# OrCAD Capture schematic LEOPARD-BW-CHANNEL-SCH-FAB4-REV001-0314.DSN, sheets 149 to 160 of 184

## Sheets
149 014_POWER OFF SEQUENCE: title: POWER OFF SEQUENCE
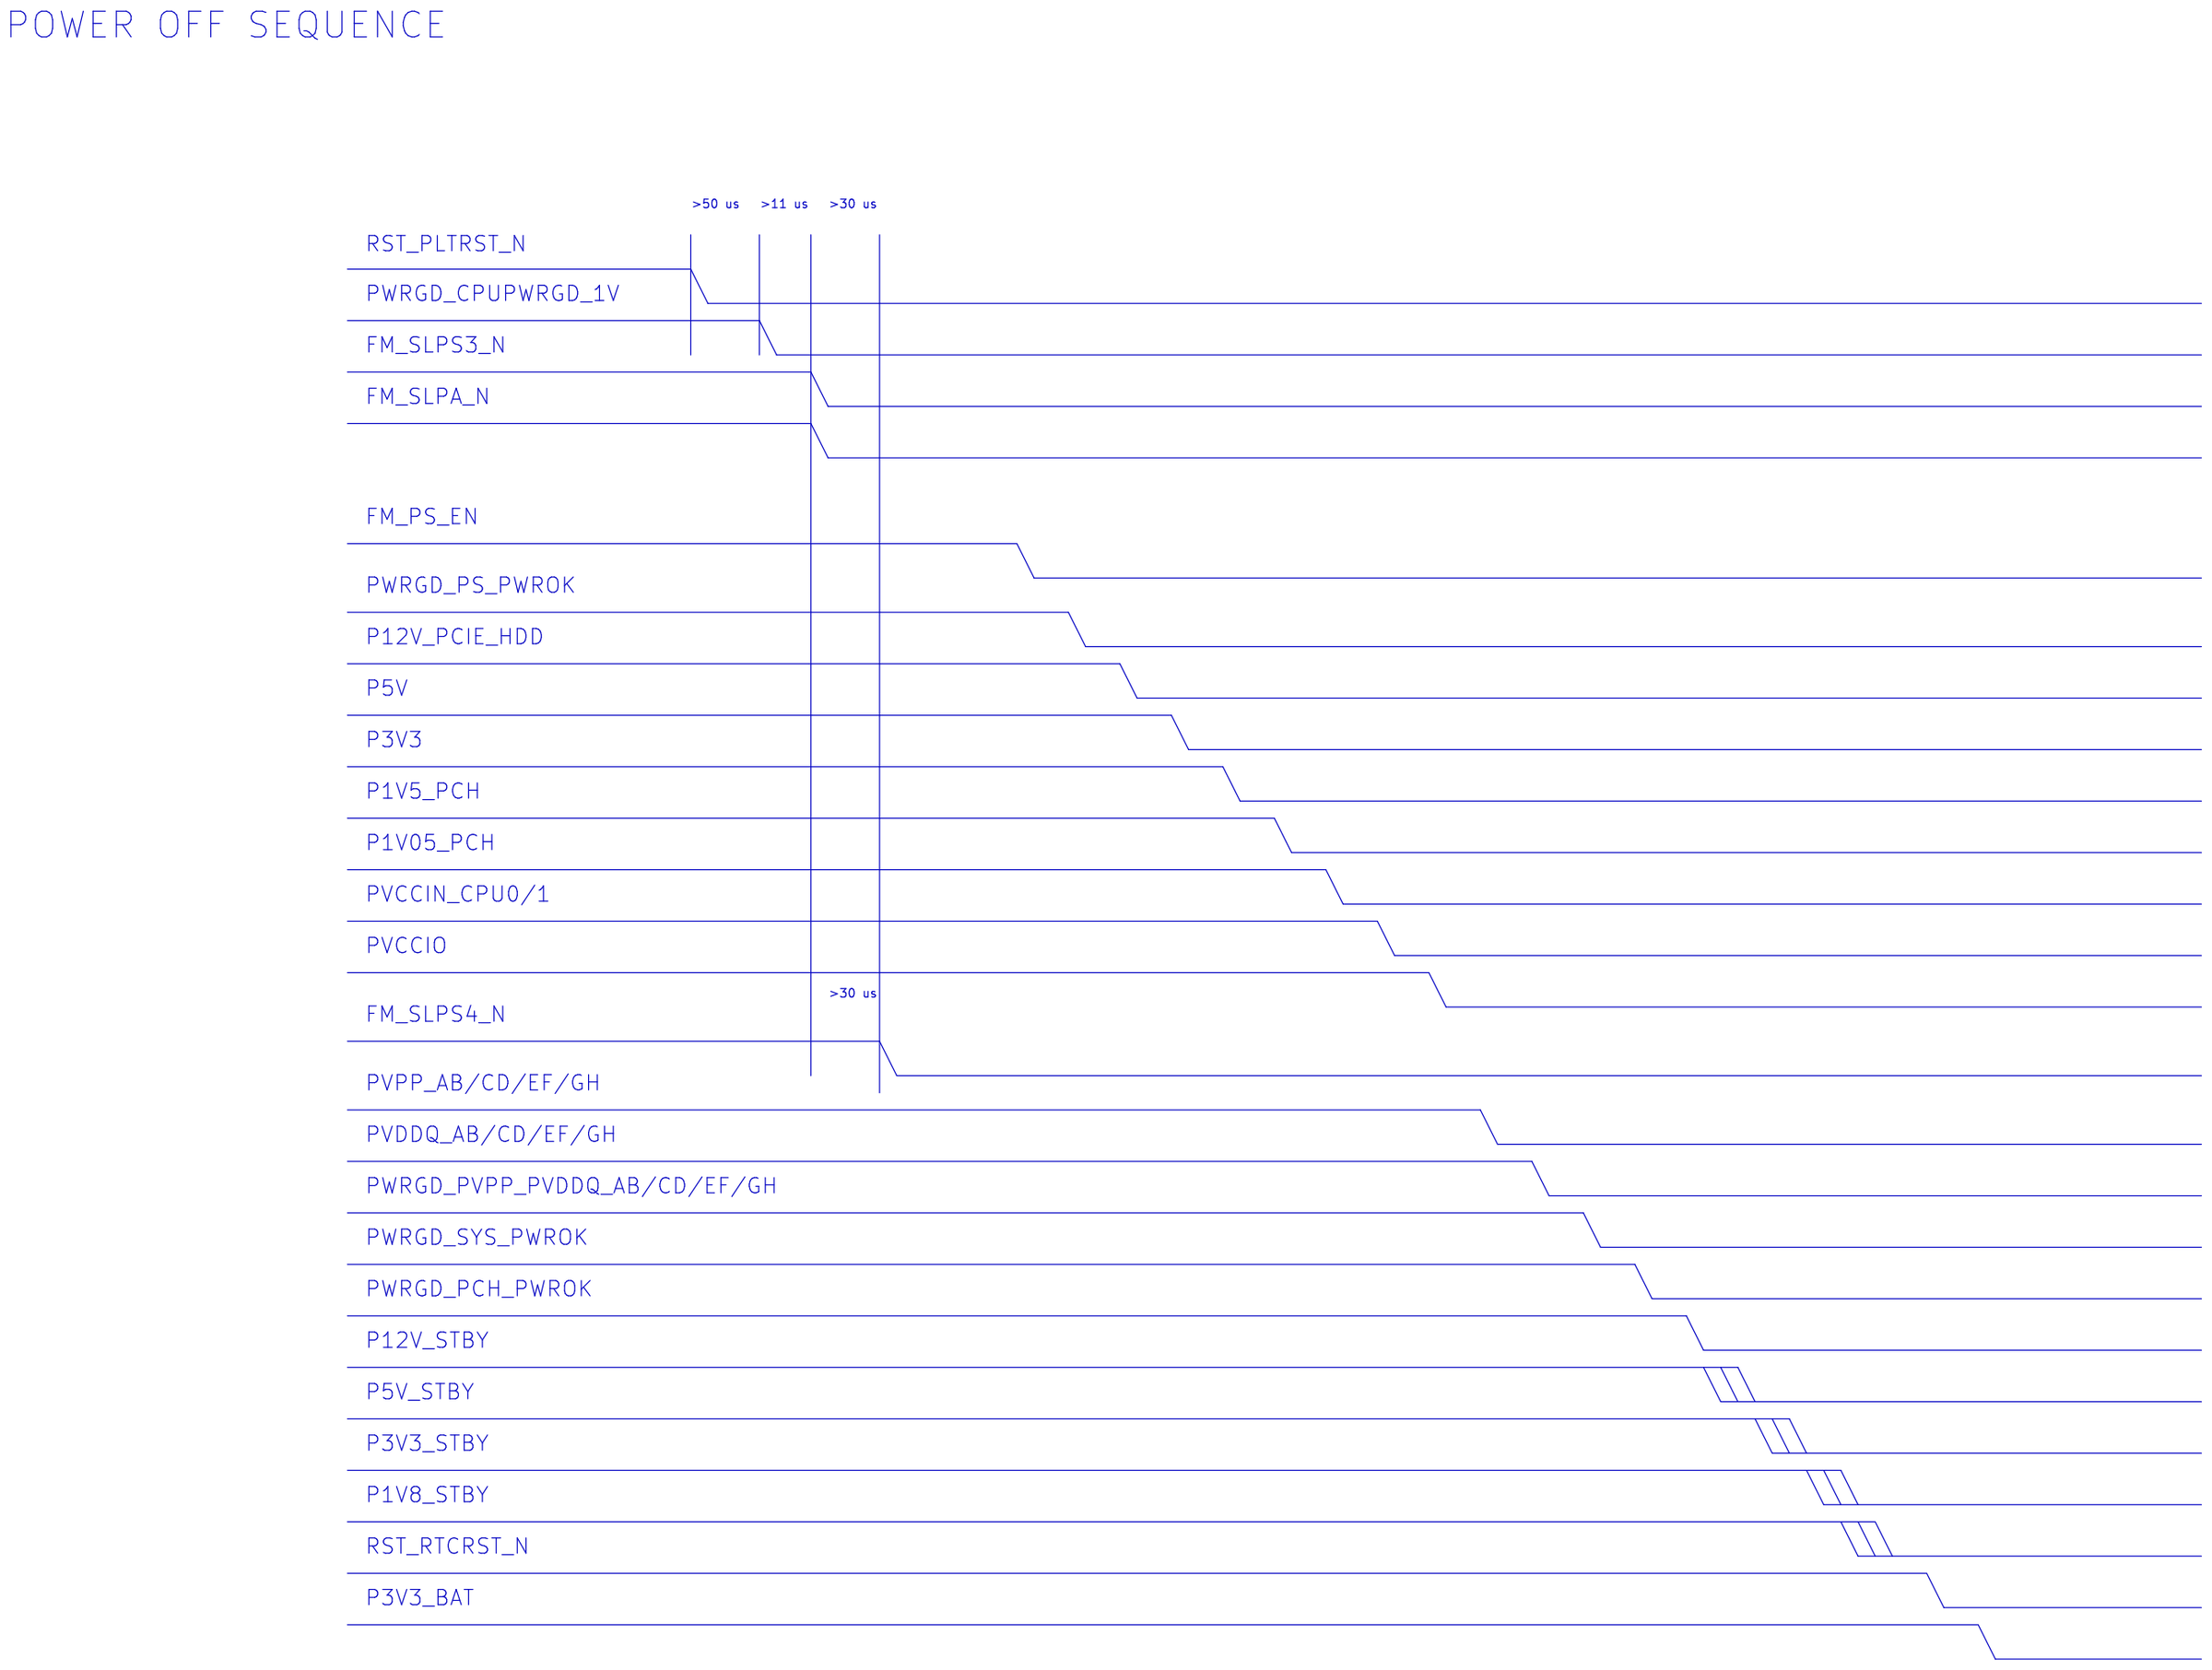
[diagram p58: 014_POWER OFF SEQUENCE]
150 013_POWER ON SEQUENCE: title: POWER ON SEQUENCE
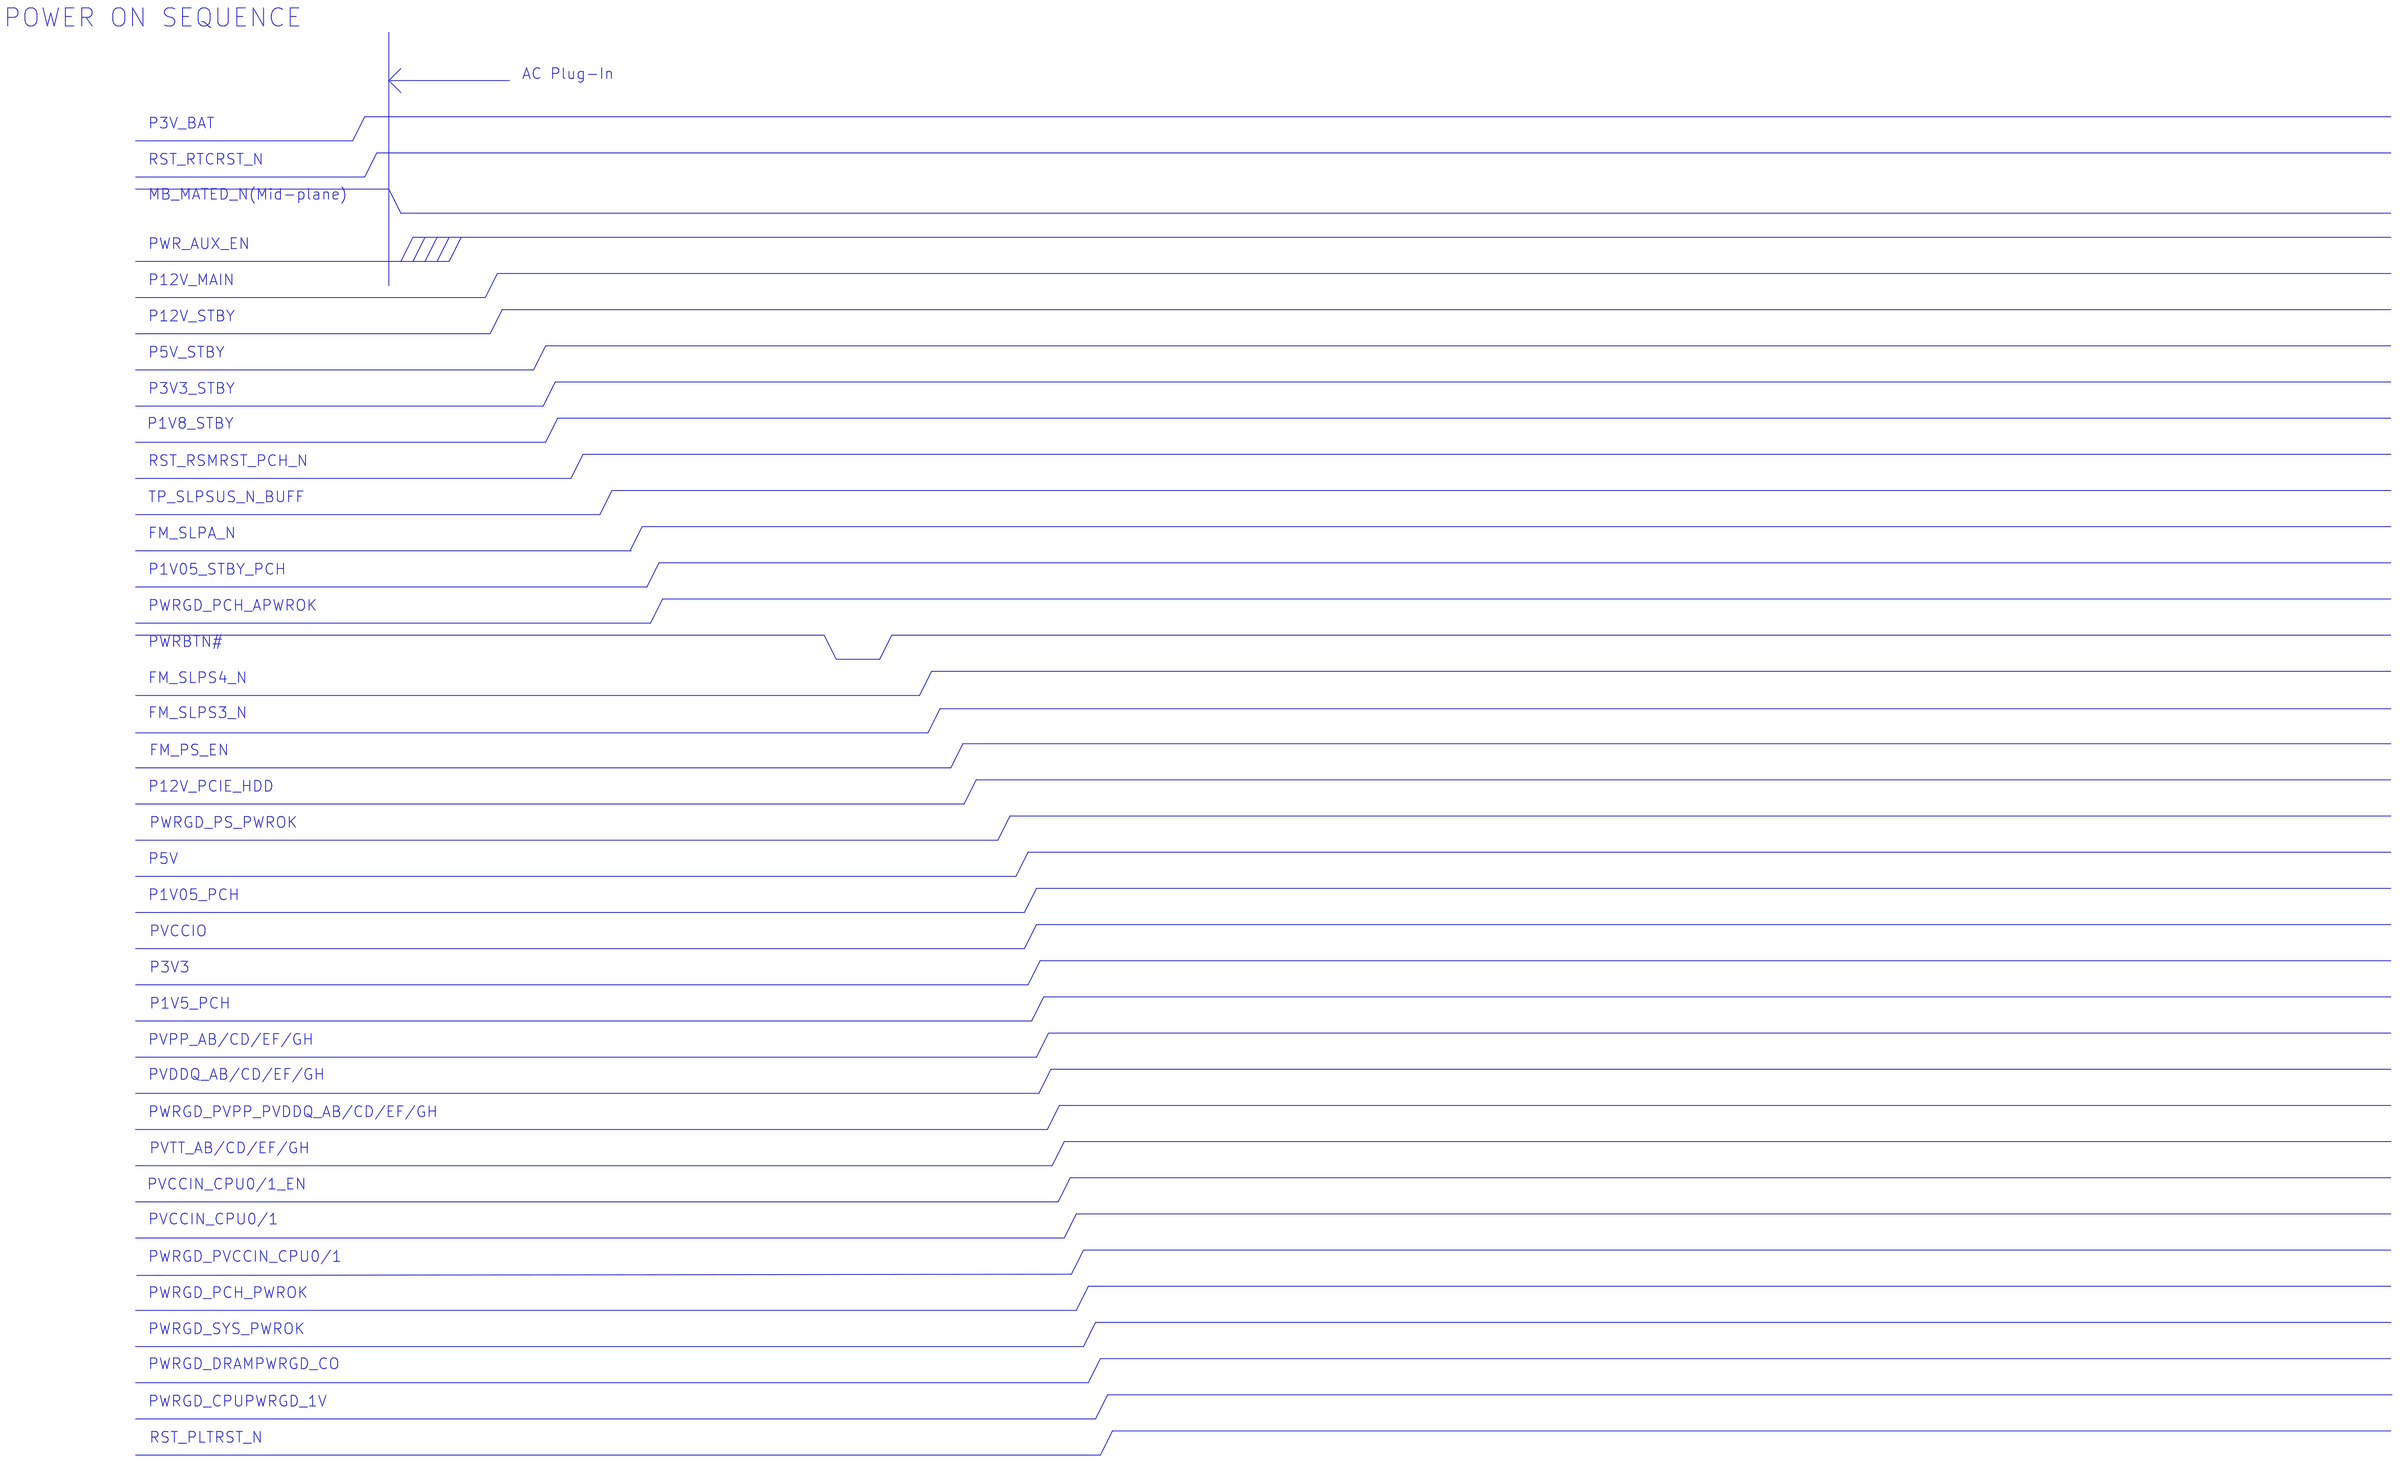
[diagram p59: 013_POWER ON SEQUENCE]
151 012_CPU XDP: title: CPU XDP
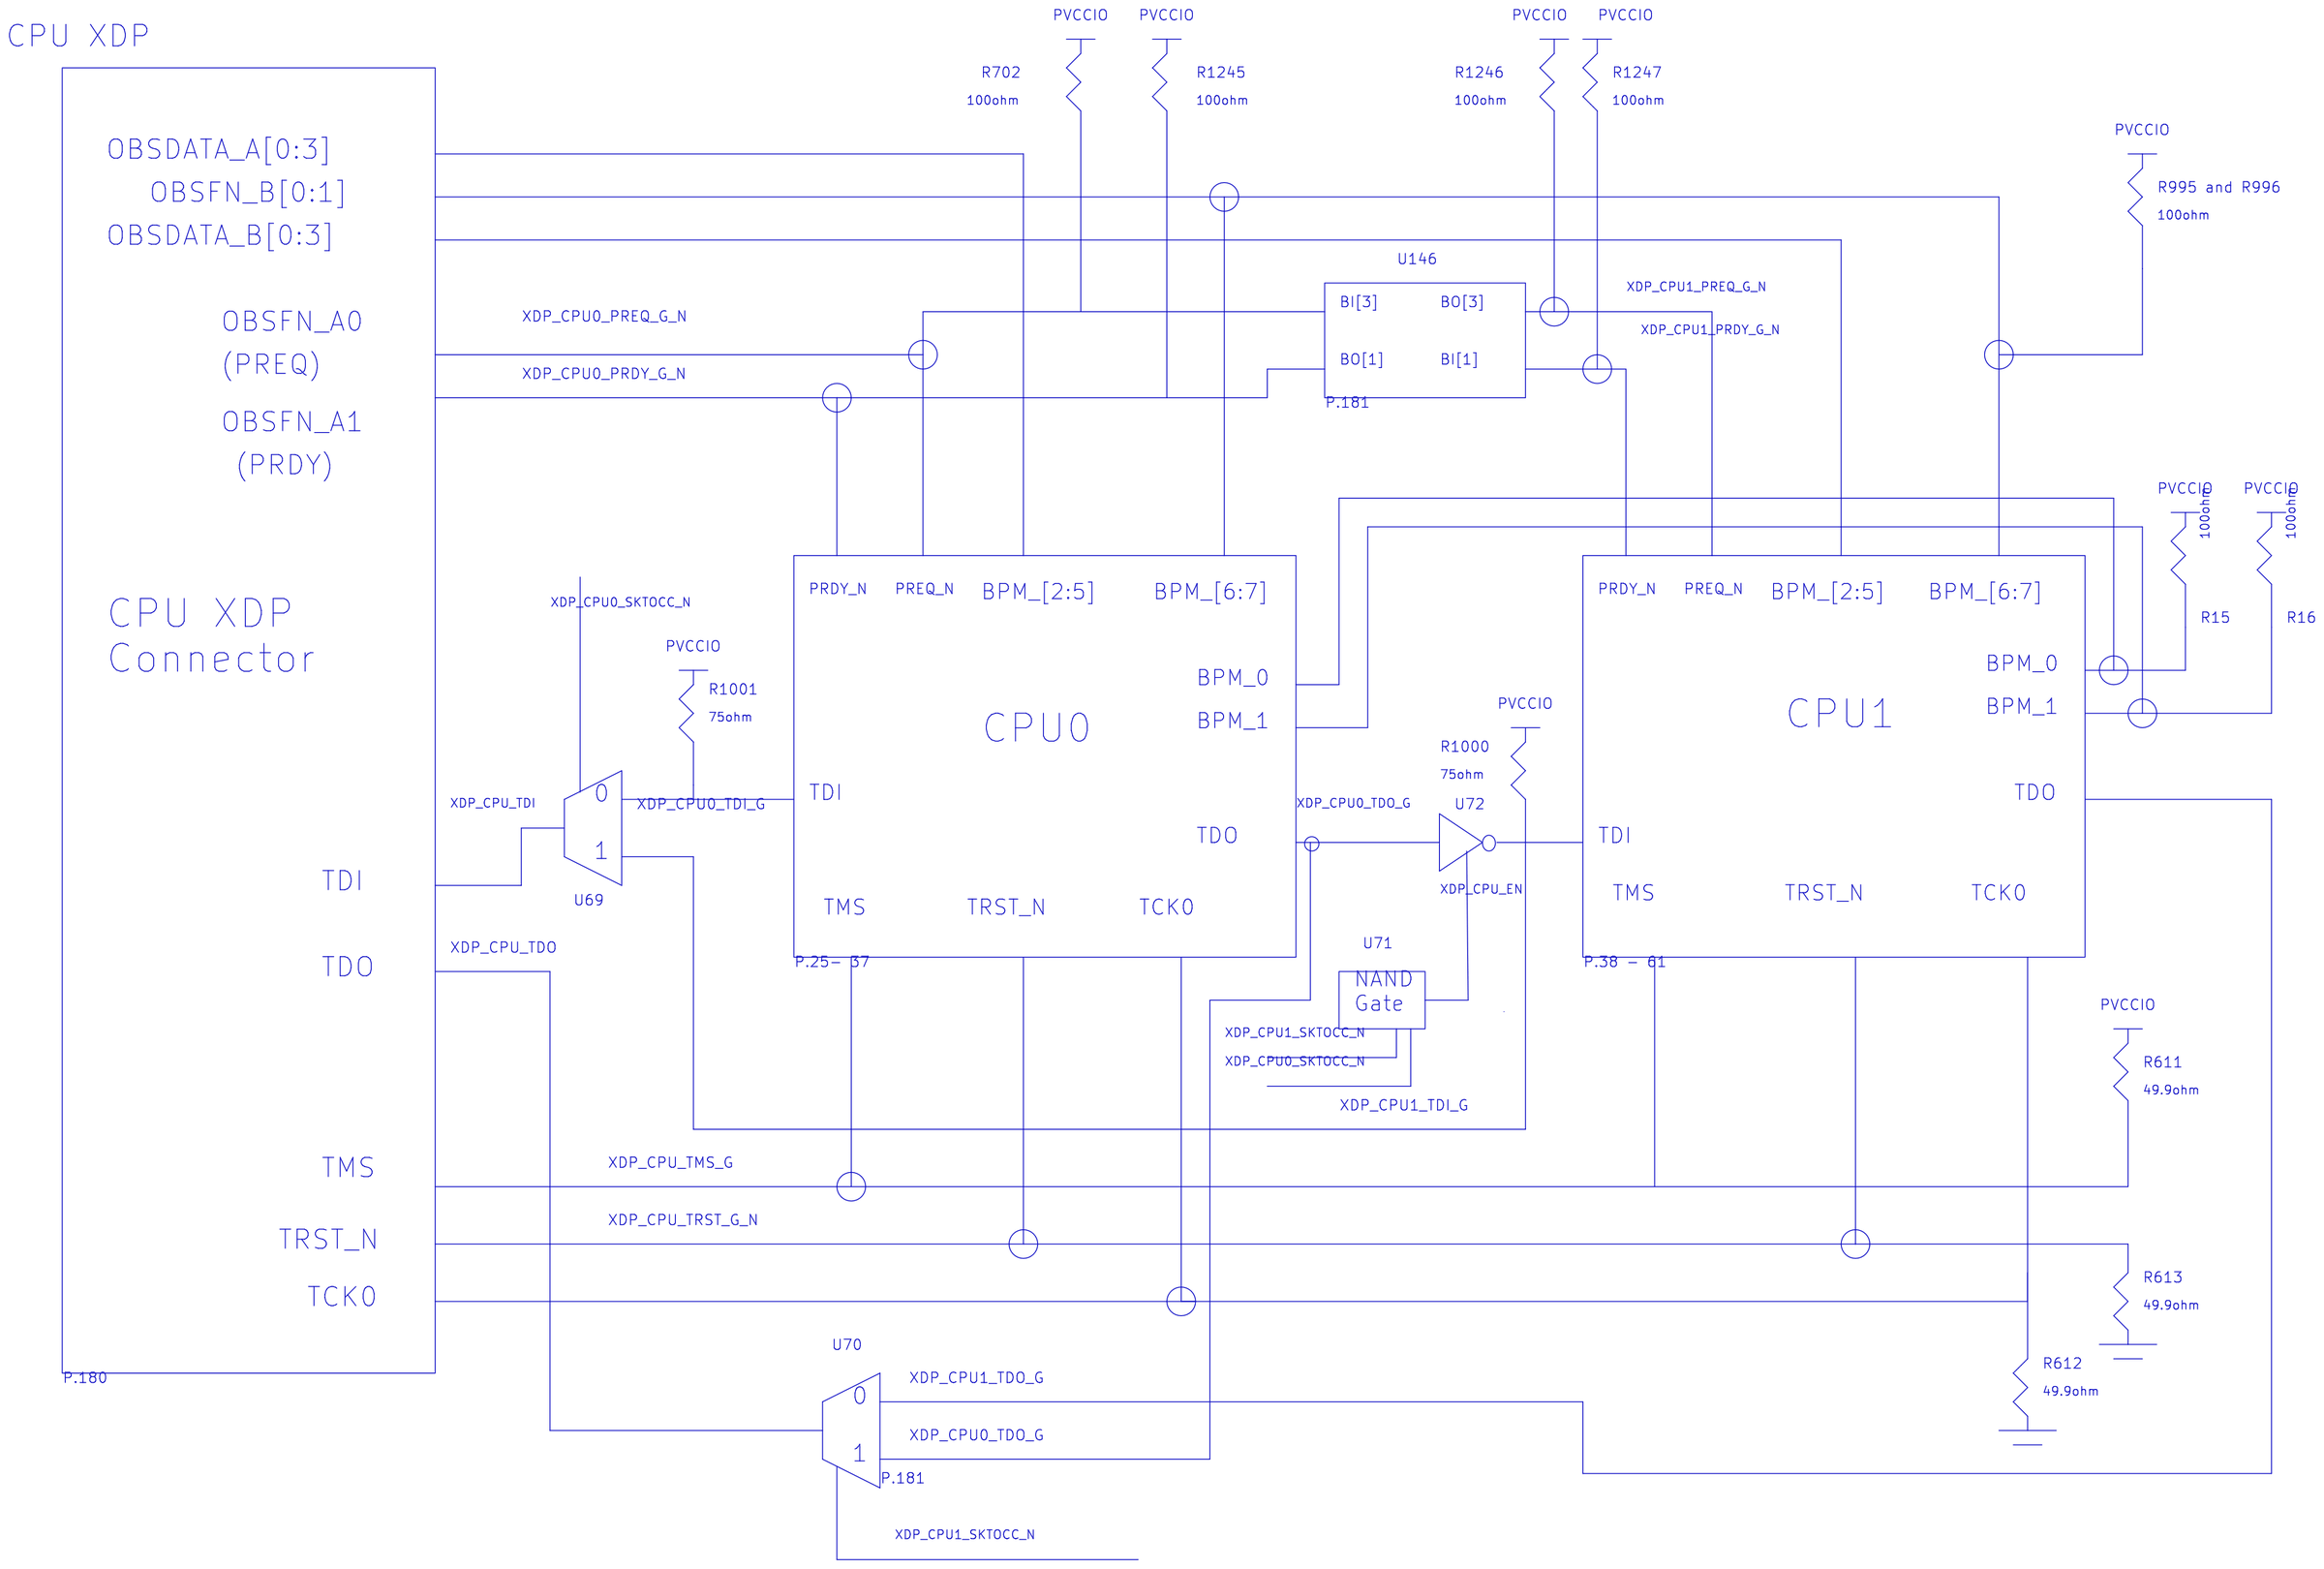
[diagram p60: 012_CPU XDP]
152 011_MEMORY WARNING AND PROTECT: title: MEMORY WARNING AND PROTECT
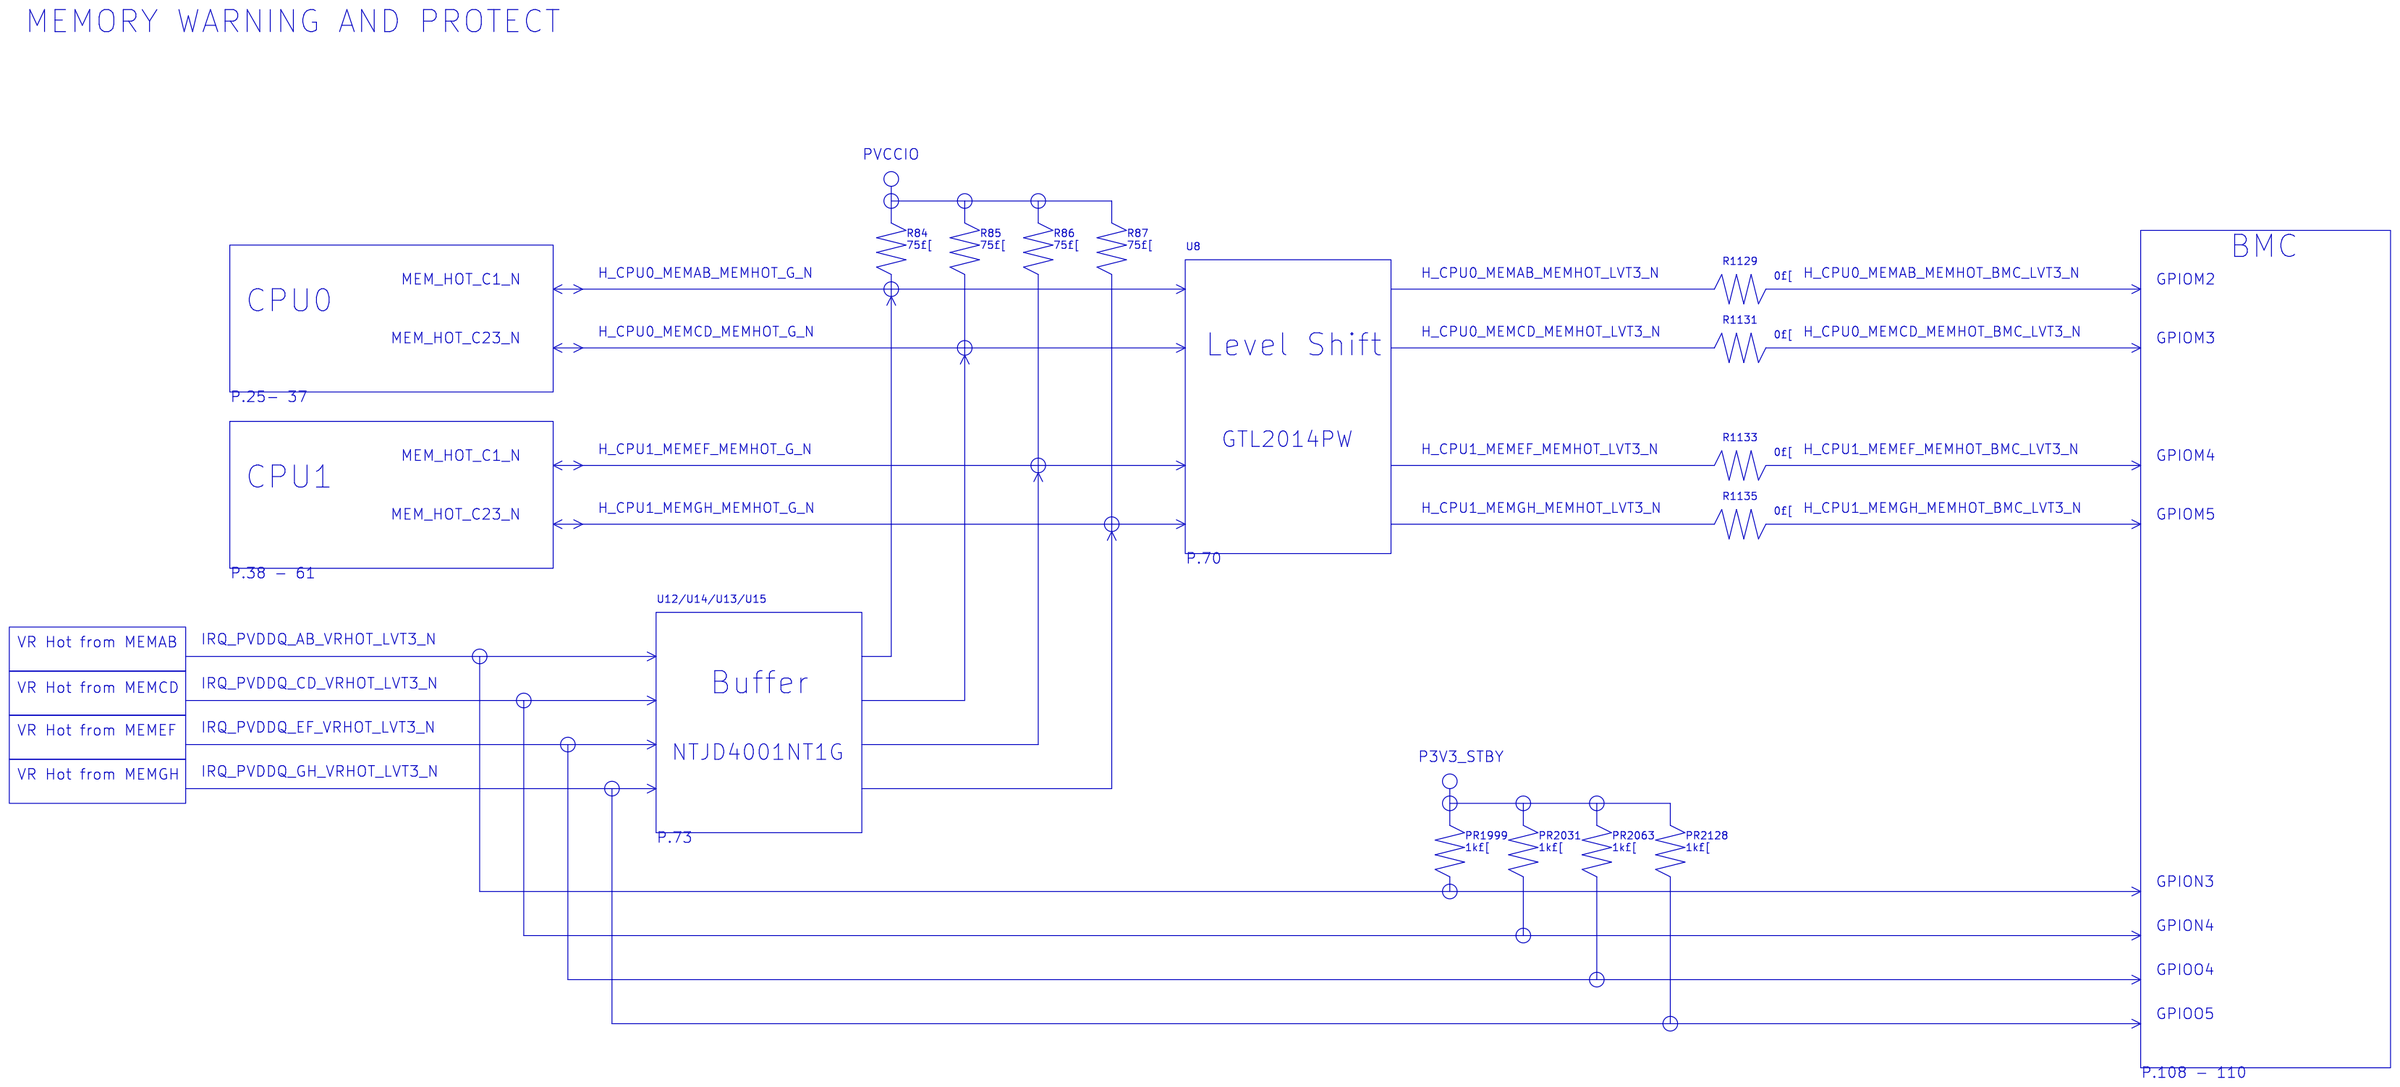
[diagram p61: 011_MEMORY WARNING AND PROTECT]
153 010_SYSTEM ERROR REPORTING: title: SYSTEM ERROR REPORTING
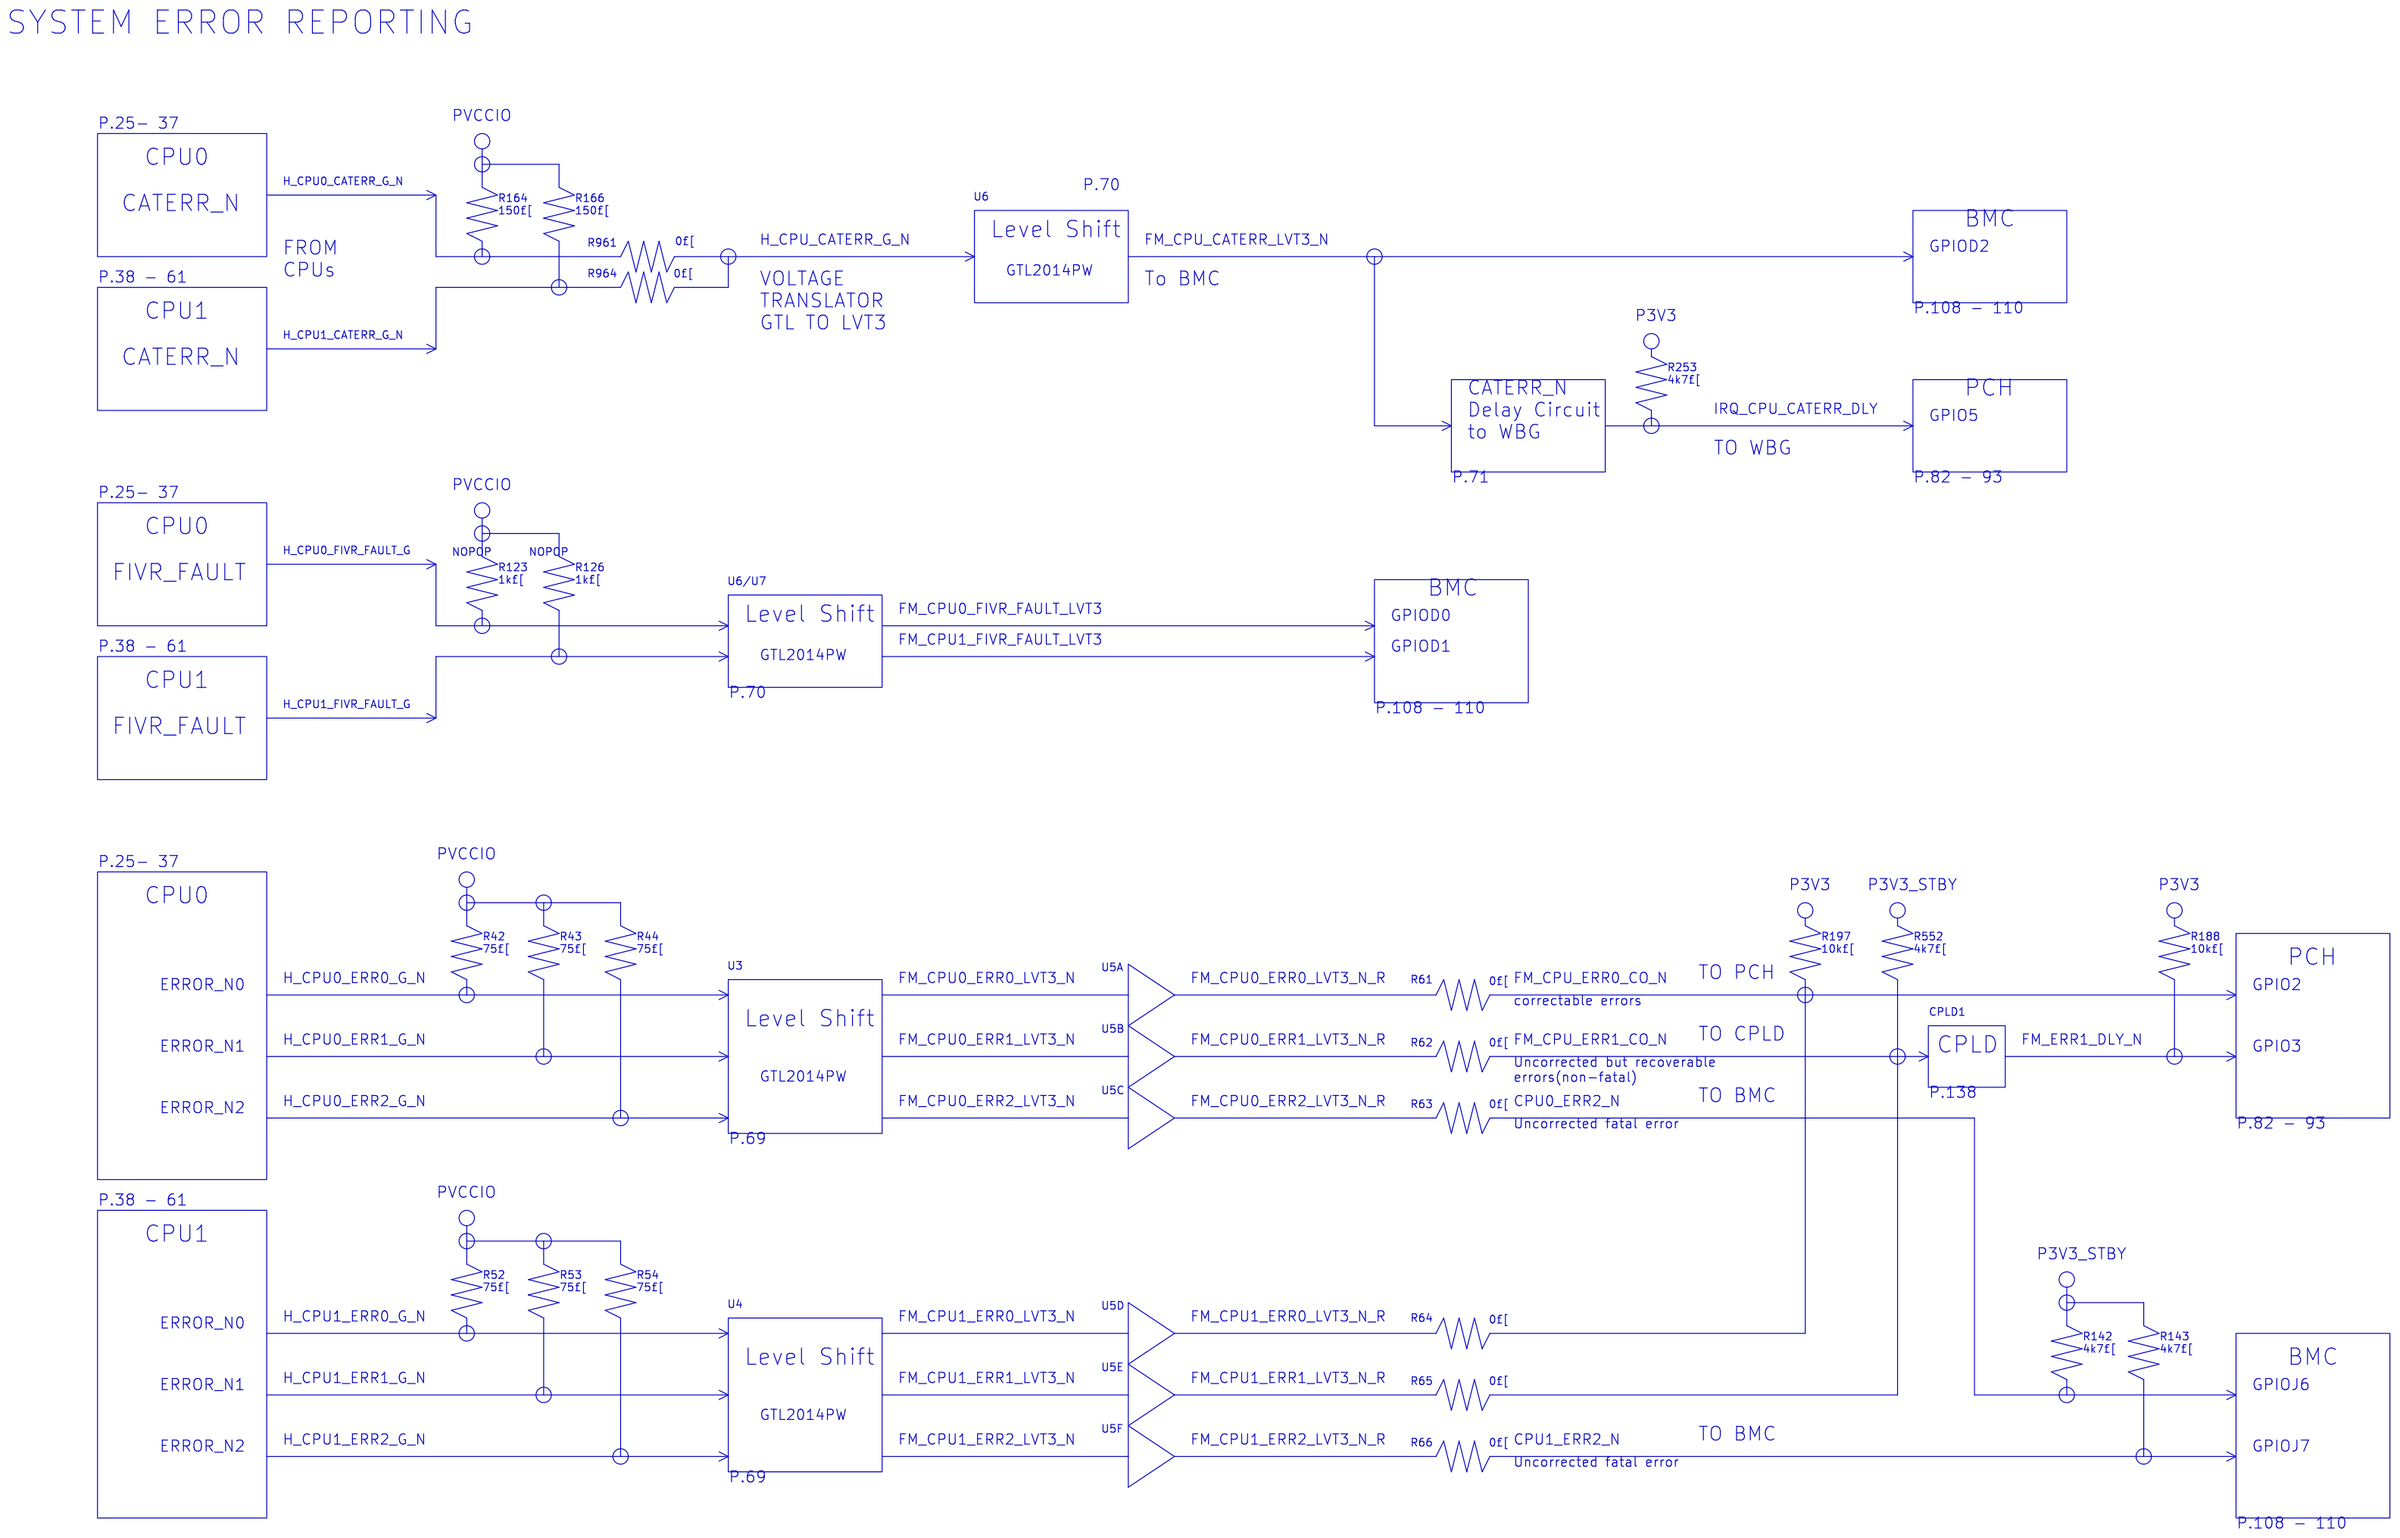
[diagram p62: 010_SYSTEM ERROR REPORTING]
154 009_SYSTEM WARNING AND PROTECT: title: SYSTEM WARNING AND PROTECT
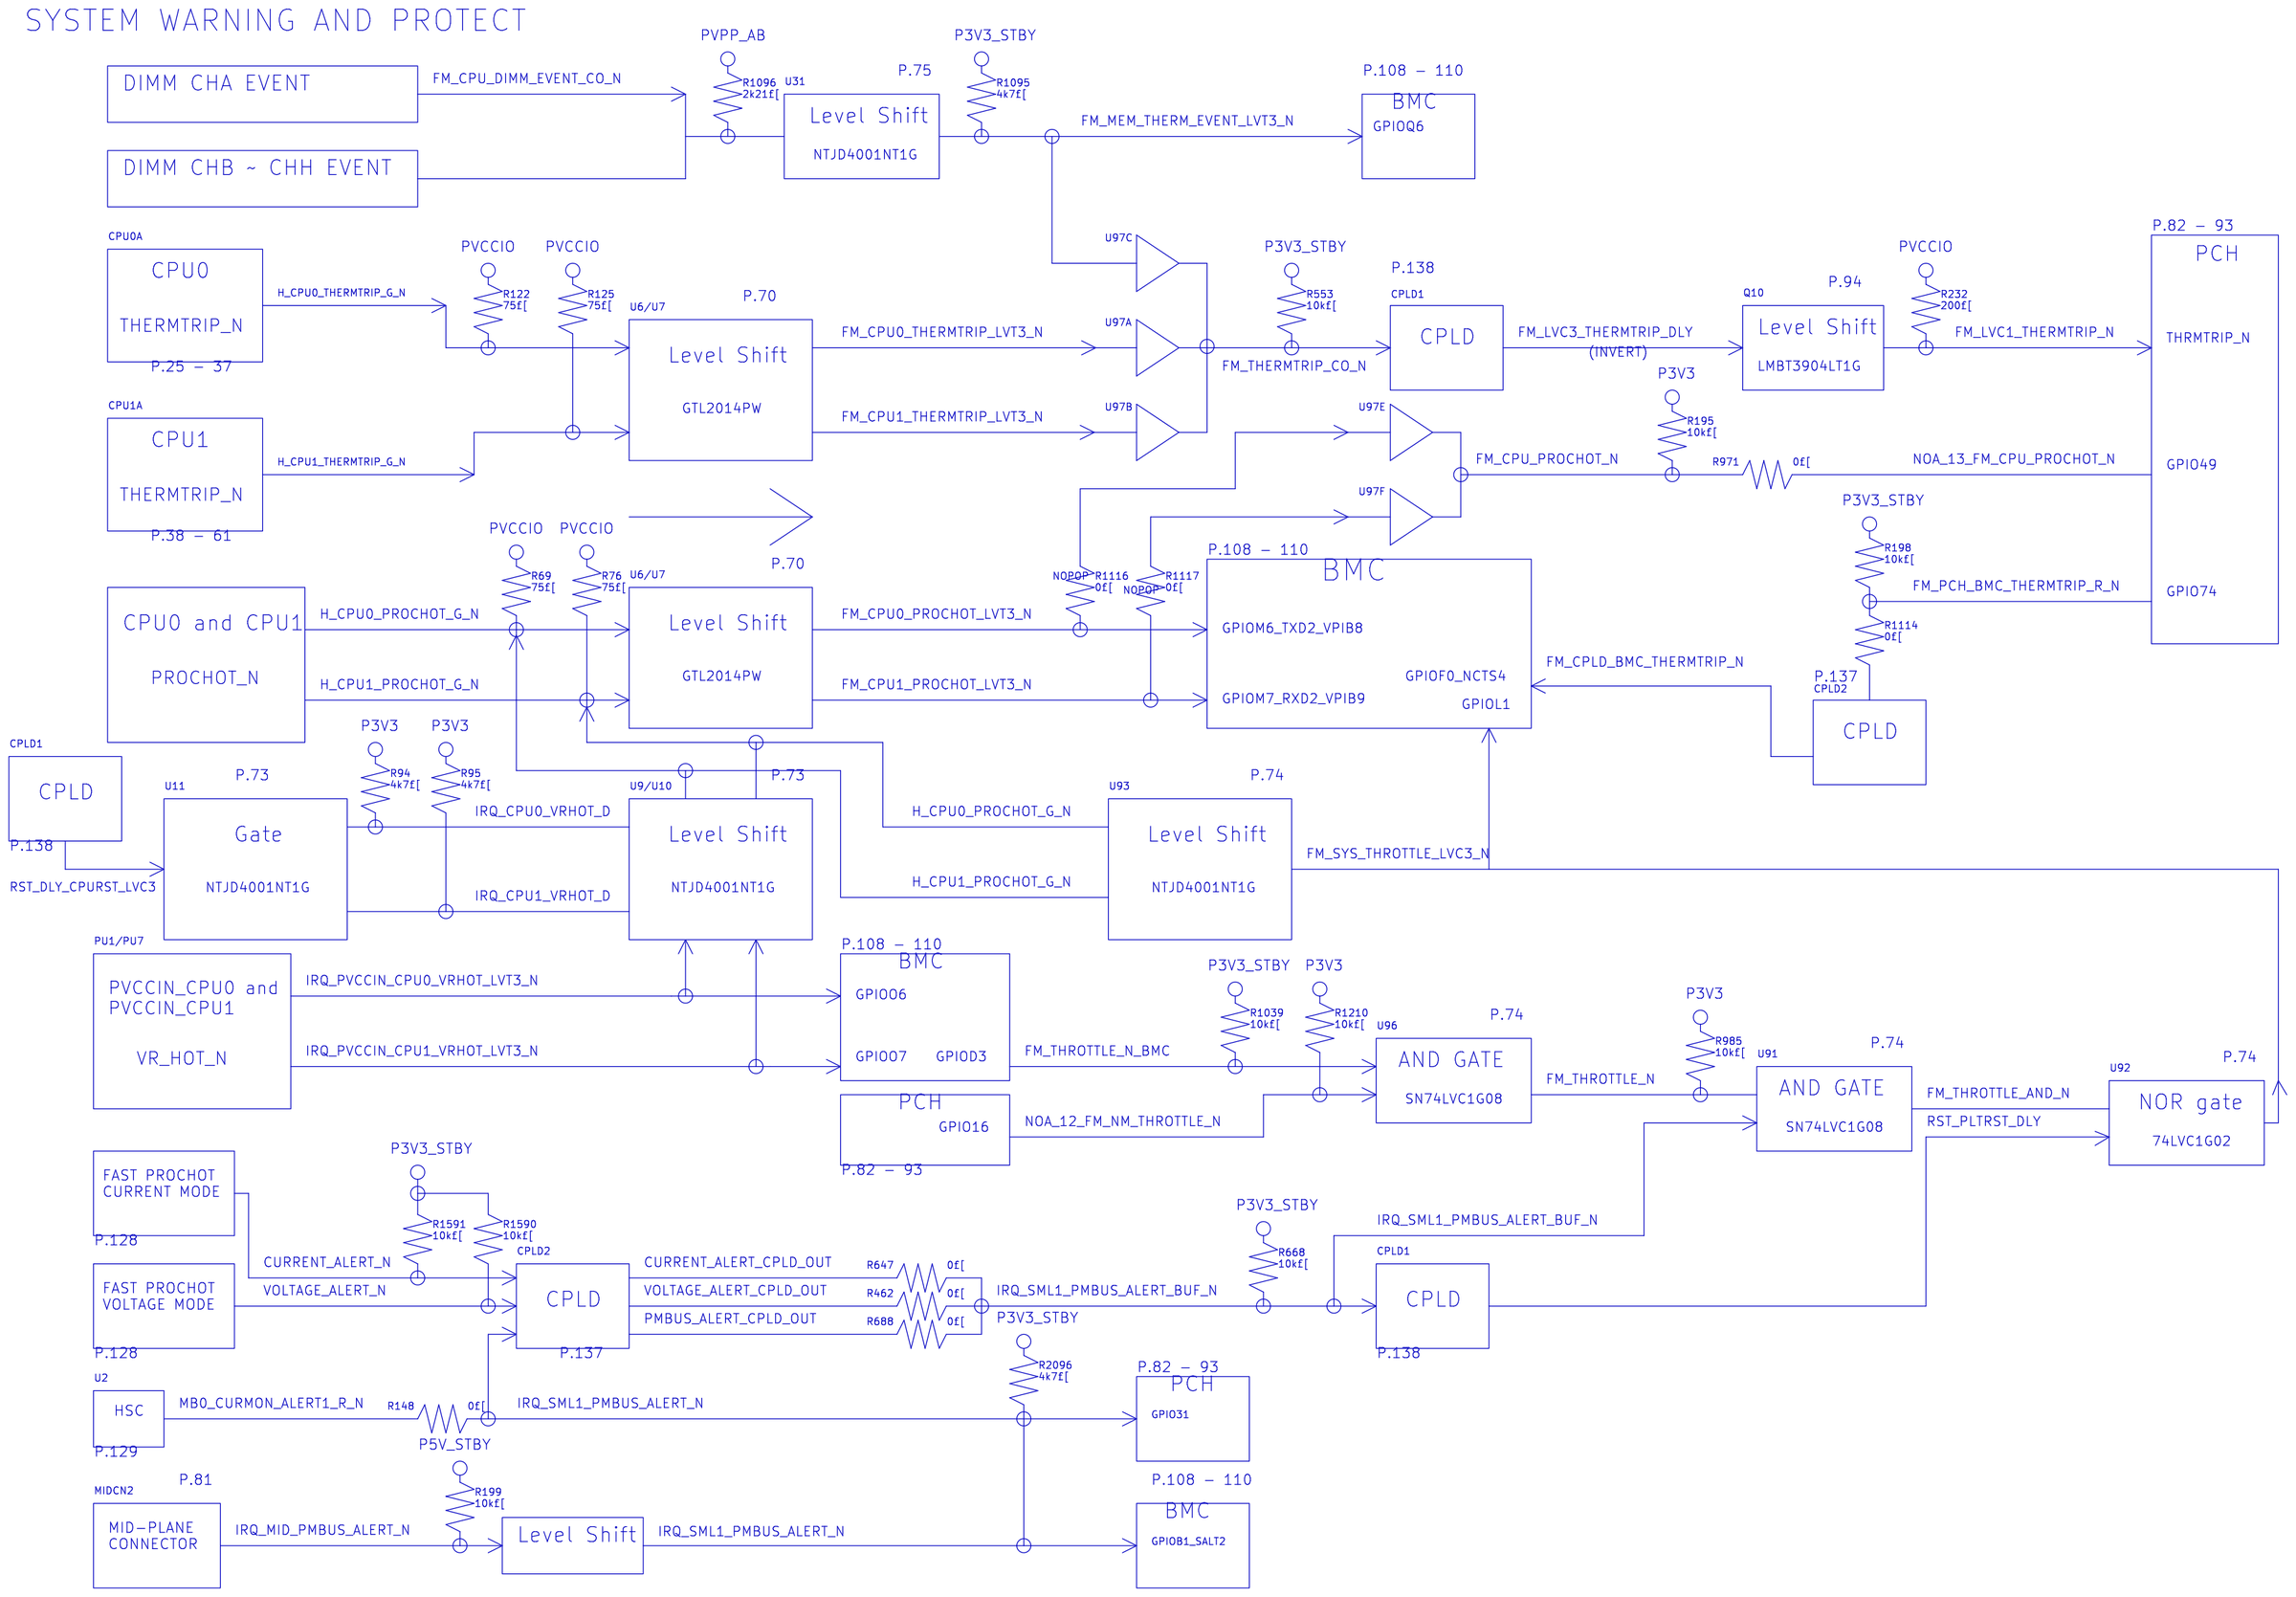
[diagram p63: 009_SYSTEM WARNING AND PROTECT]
155 005_POWER DISTRIBUTION DIAGRAM: title: POWER DISTRIBUTION DIAGRAM
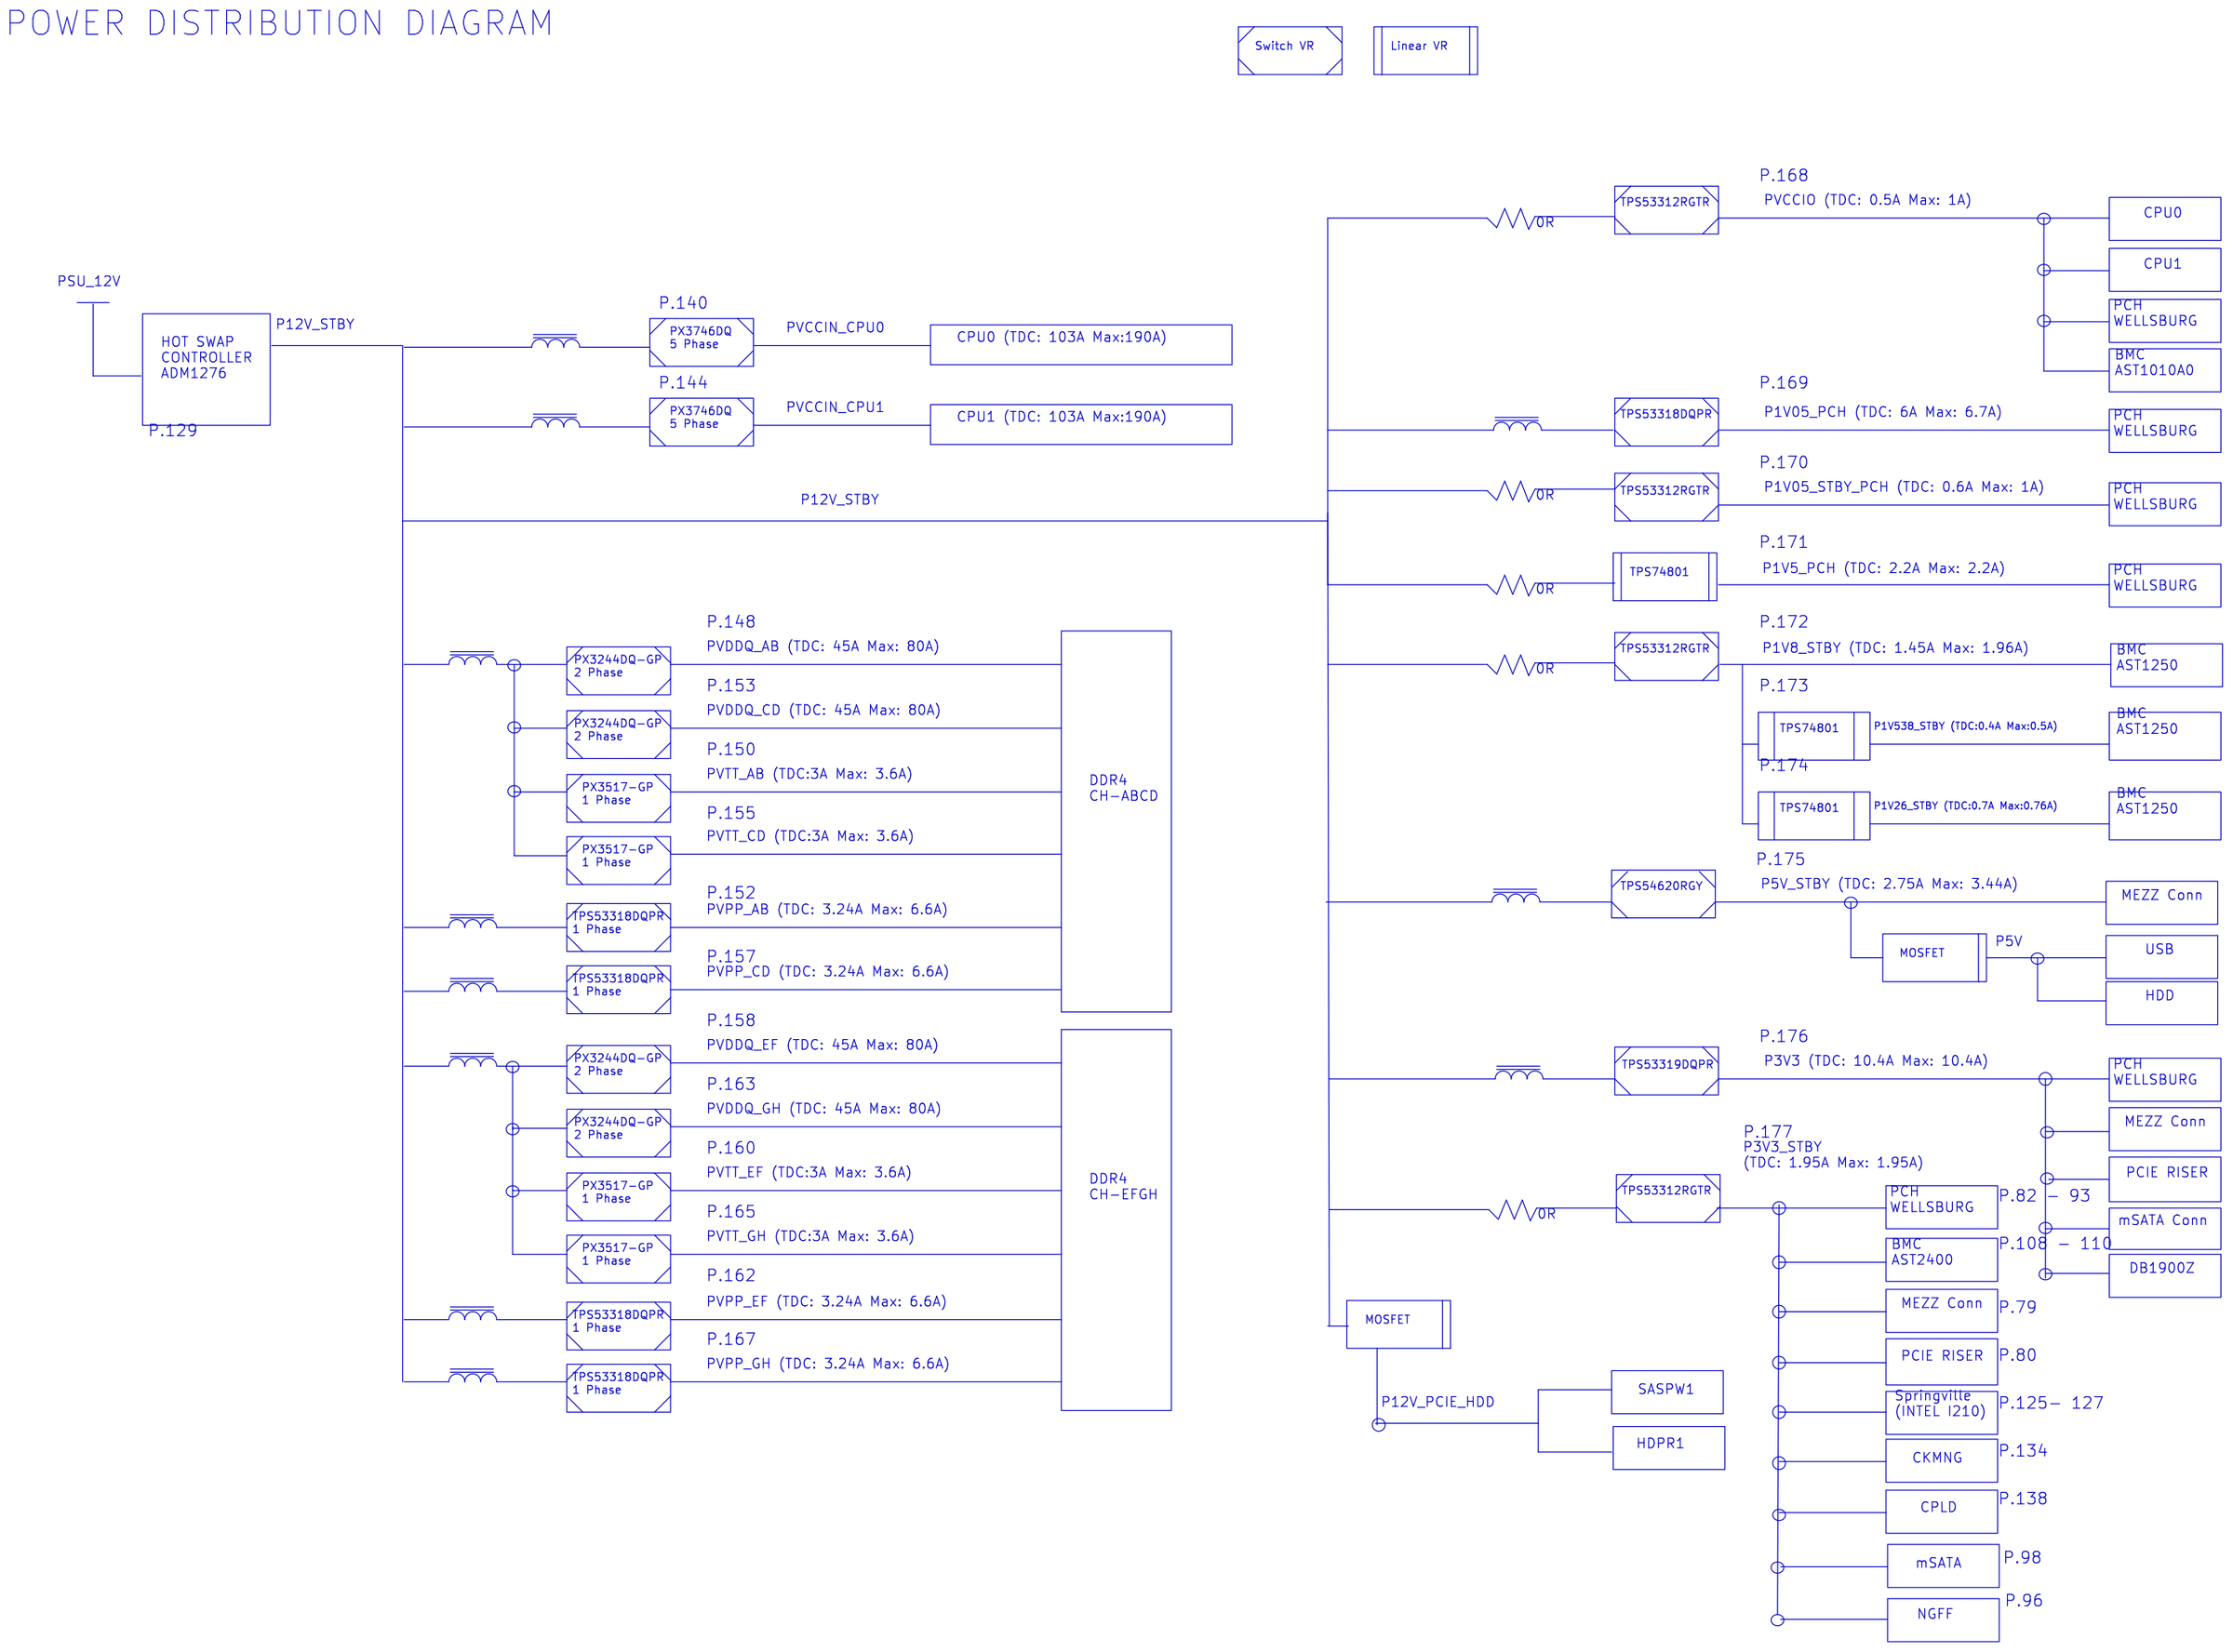
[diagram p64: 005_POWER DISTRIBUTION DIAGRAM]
156 003_BLOCK DIAGRAM: title: BLOCK DIAGRAM
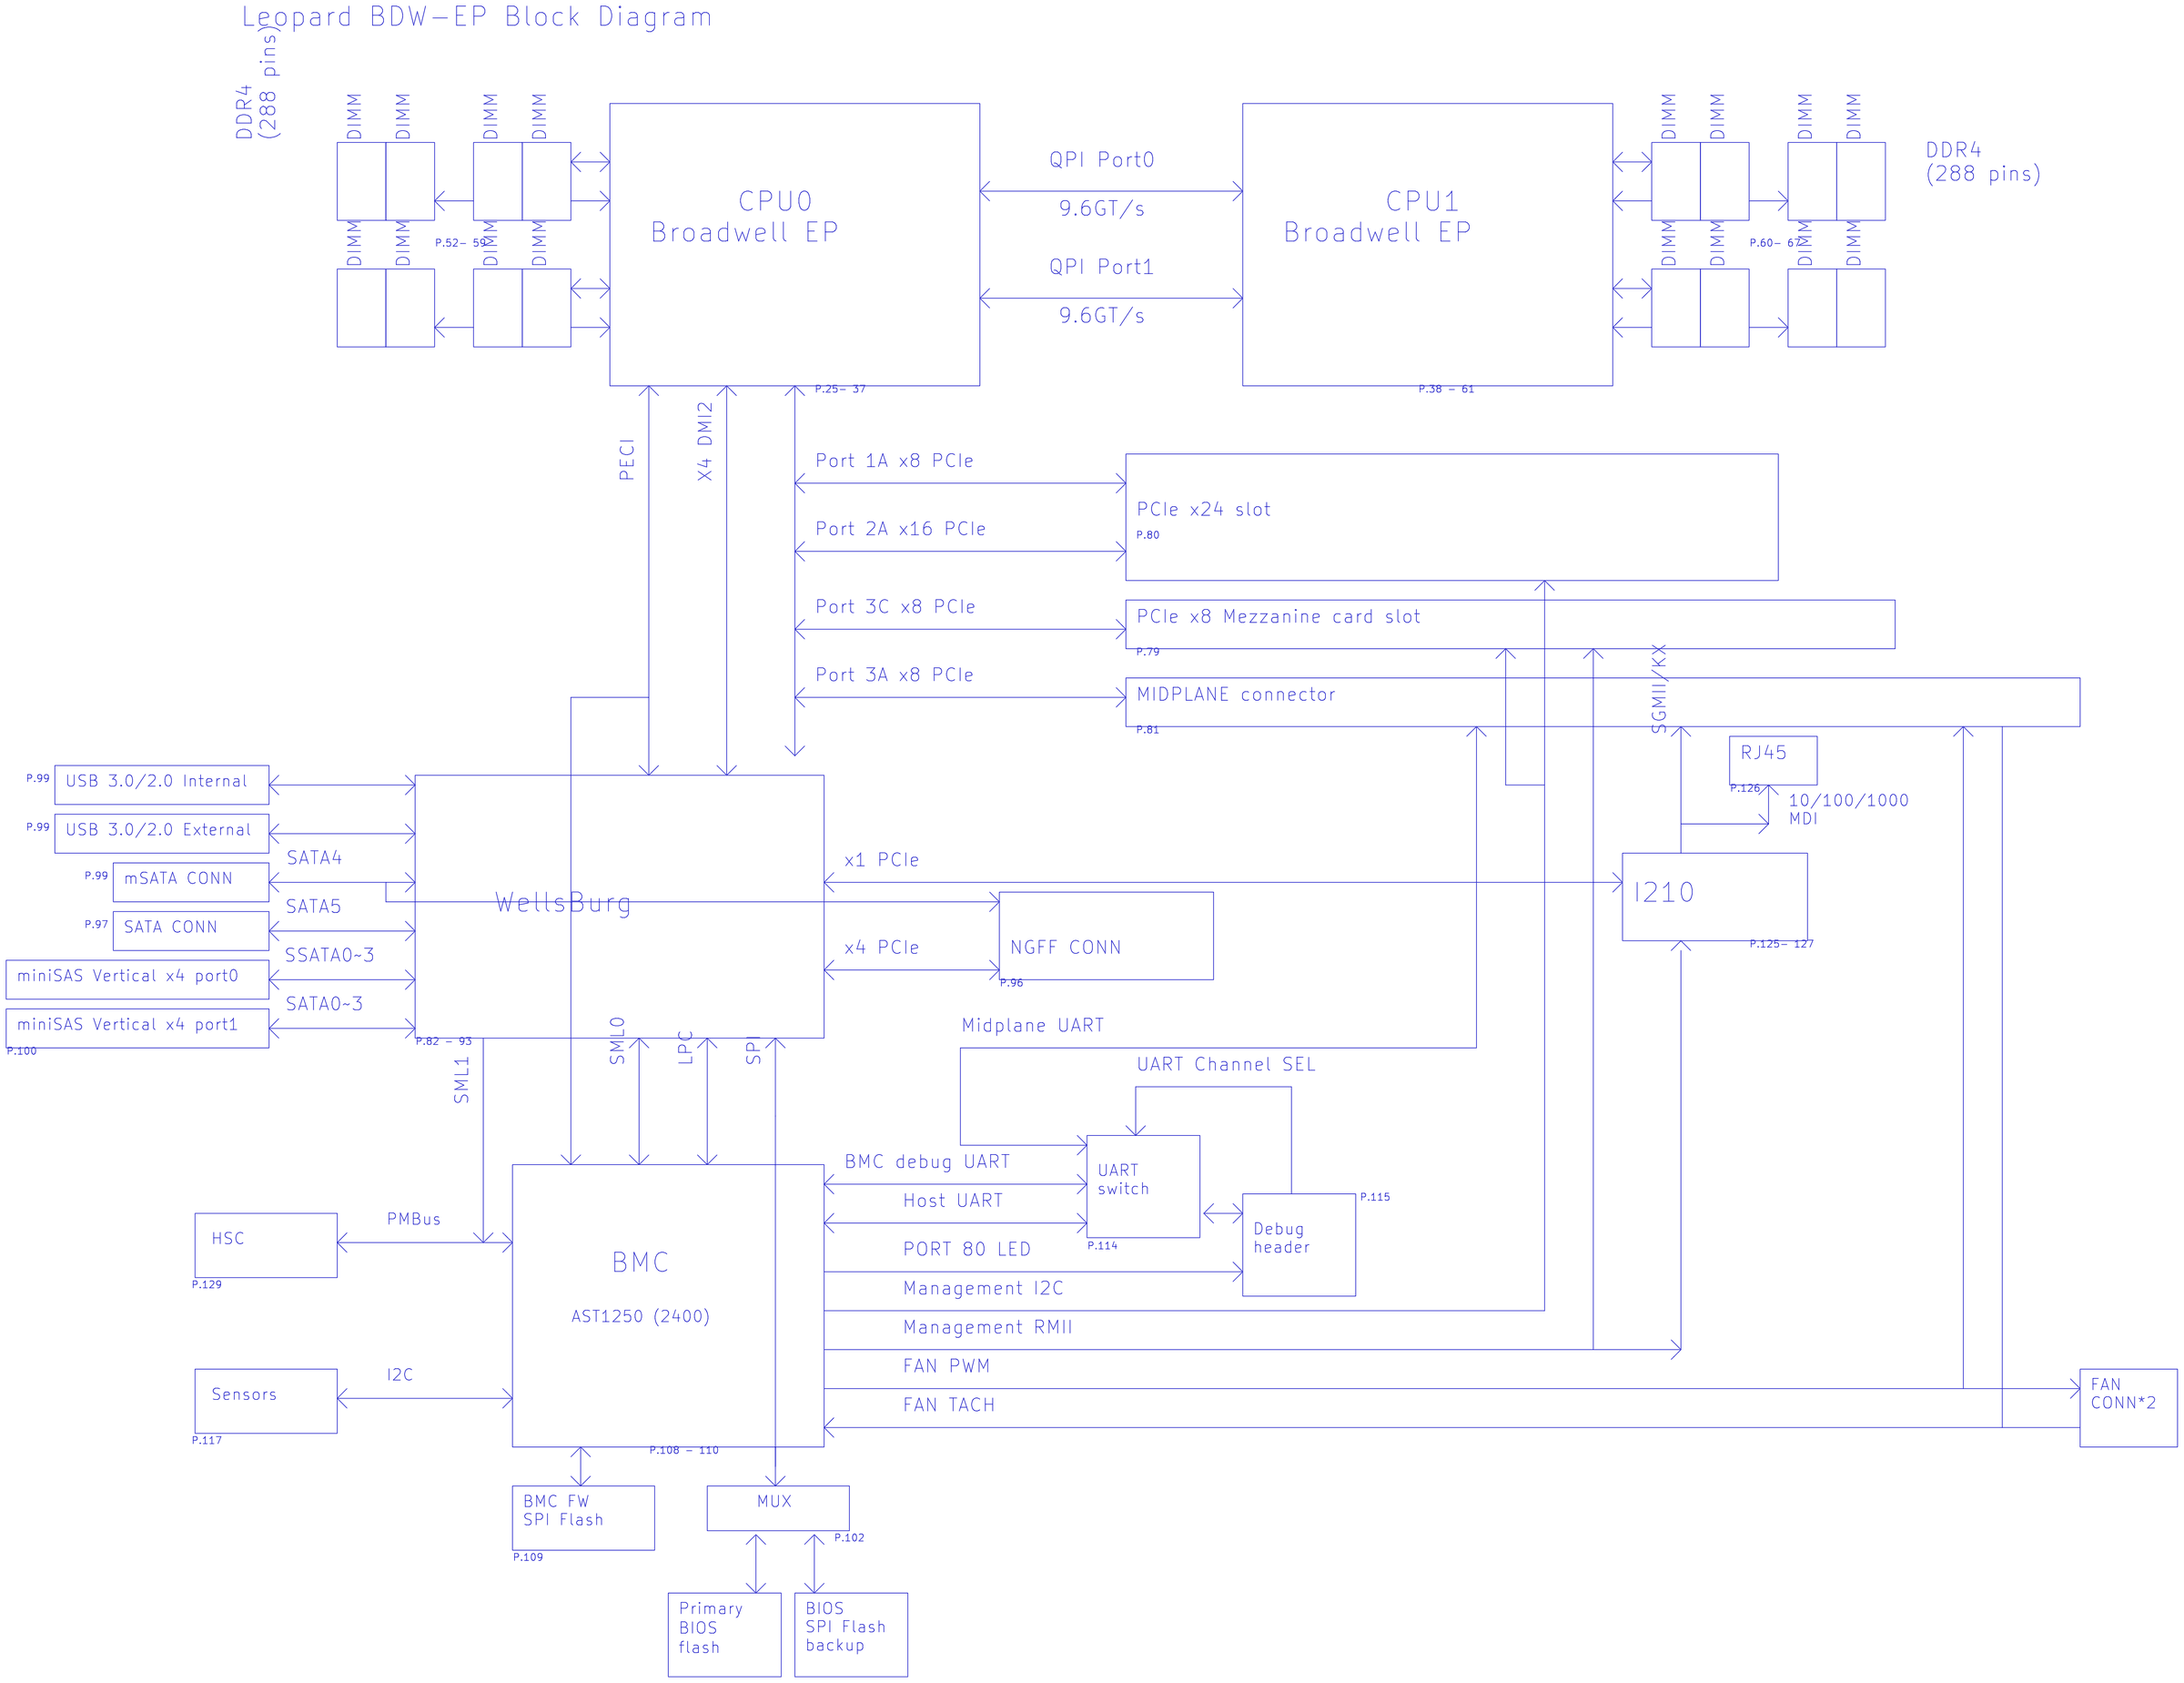
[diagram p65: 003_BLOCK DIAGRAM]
157 002_INDEX: title: INDEX
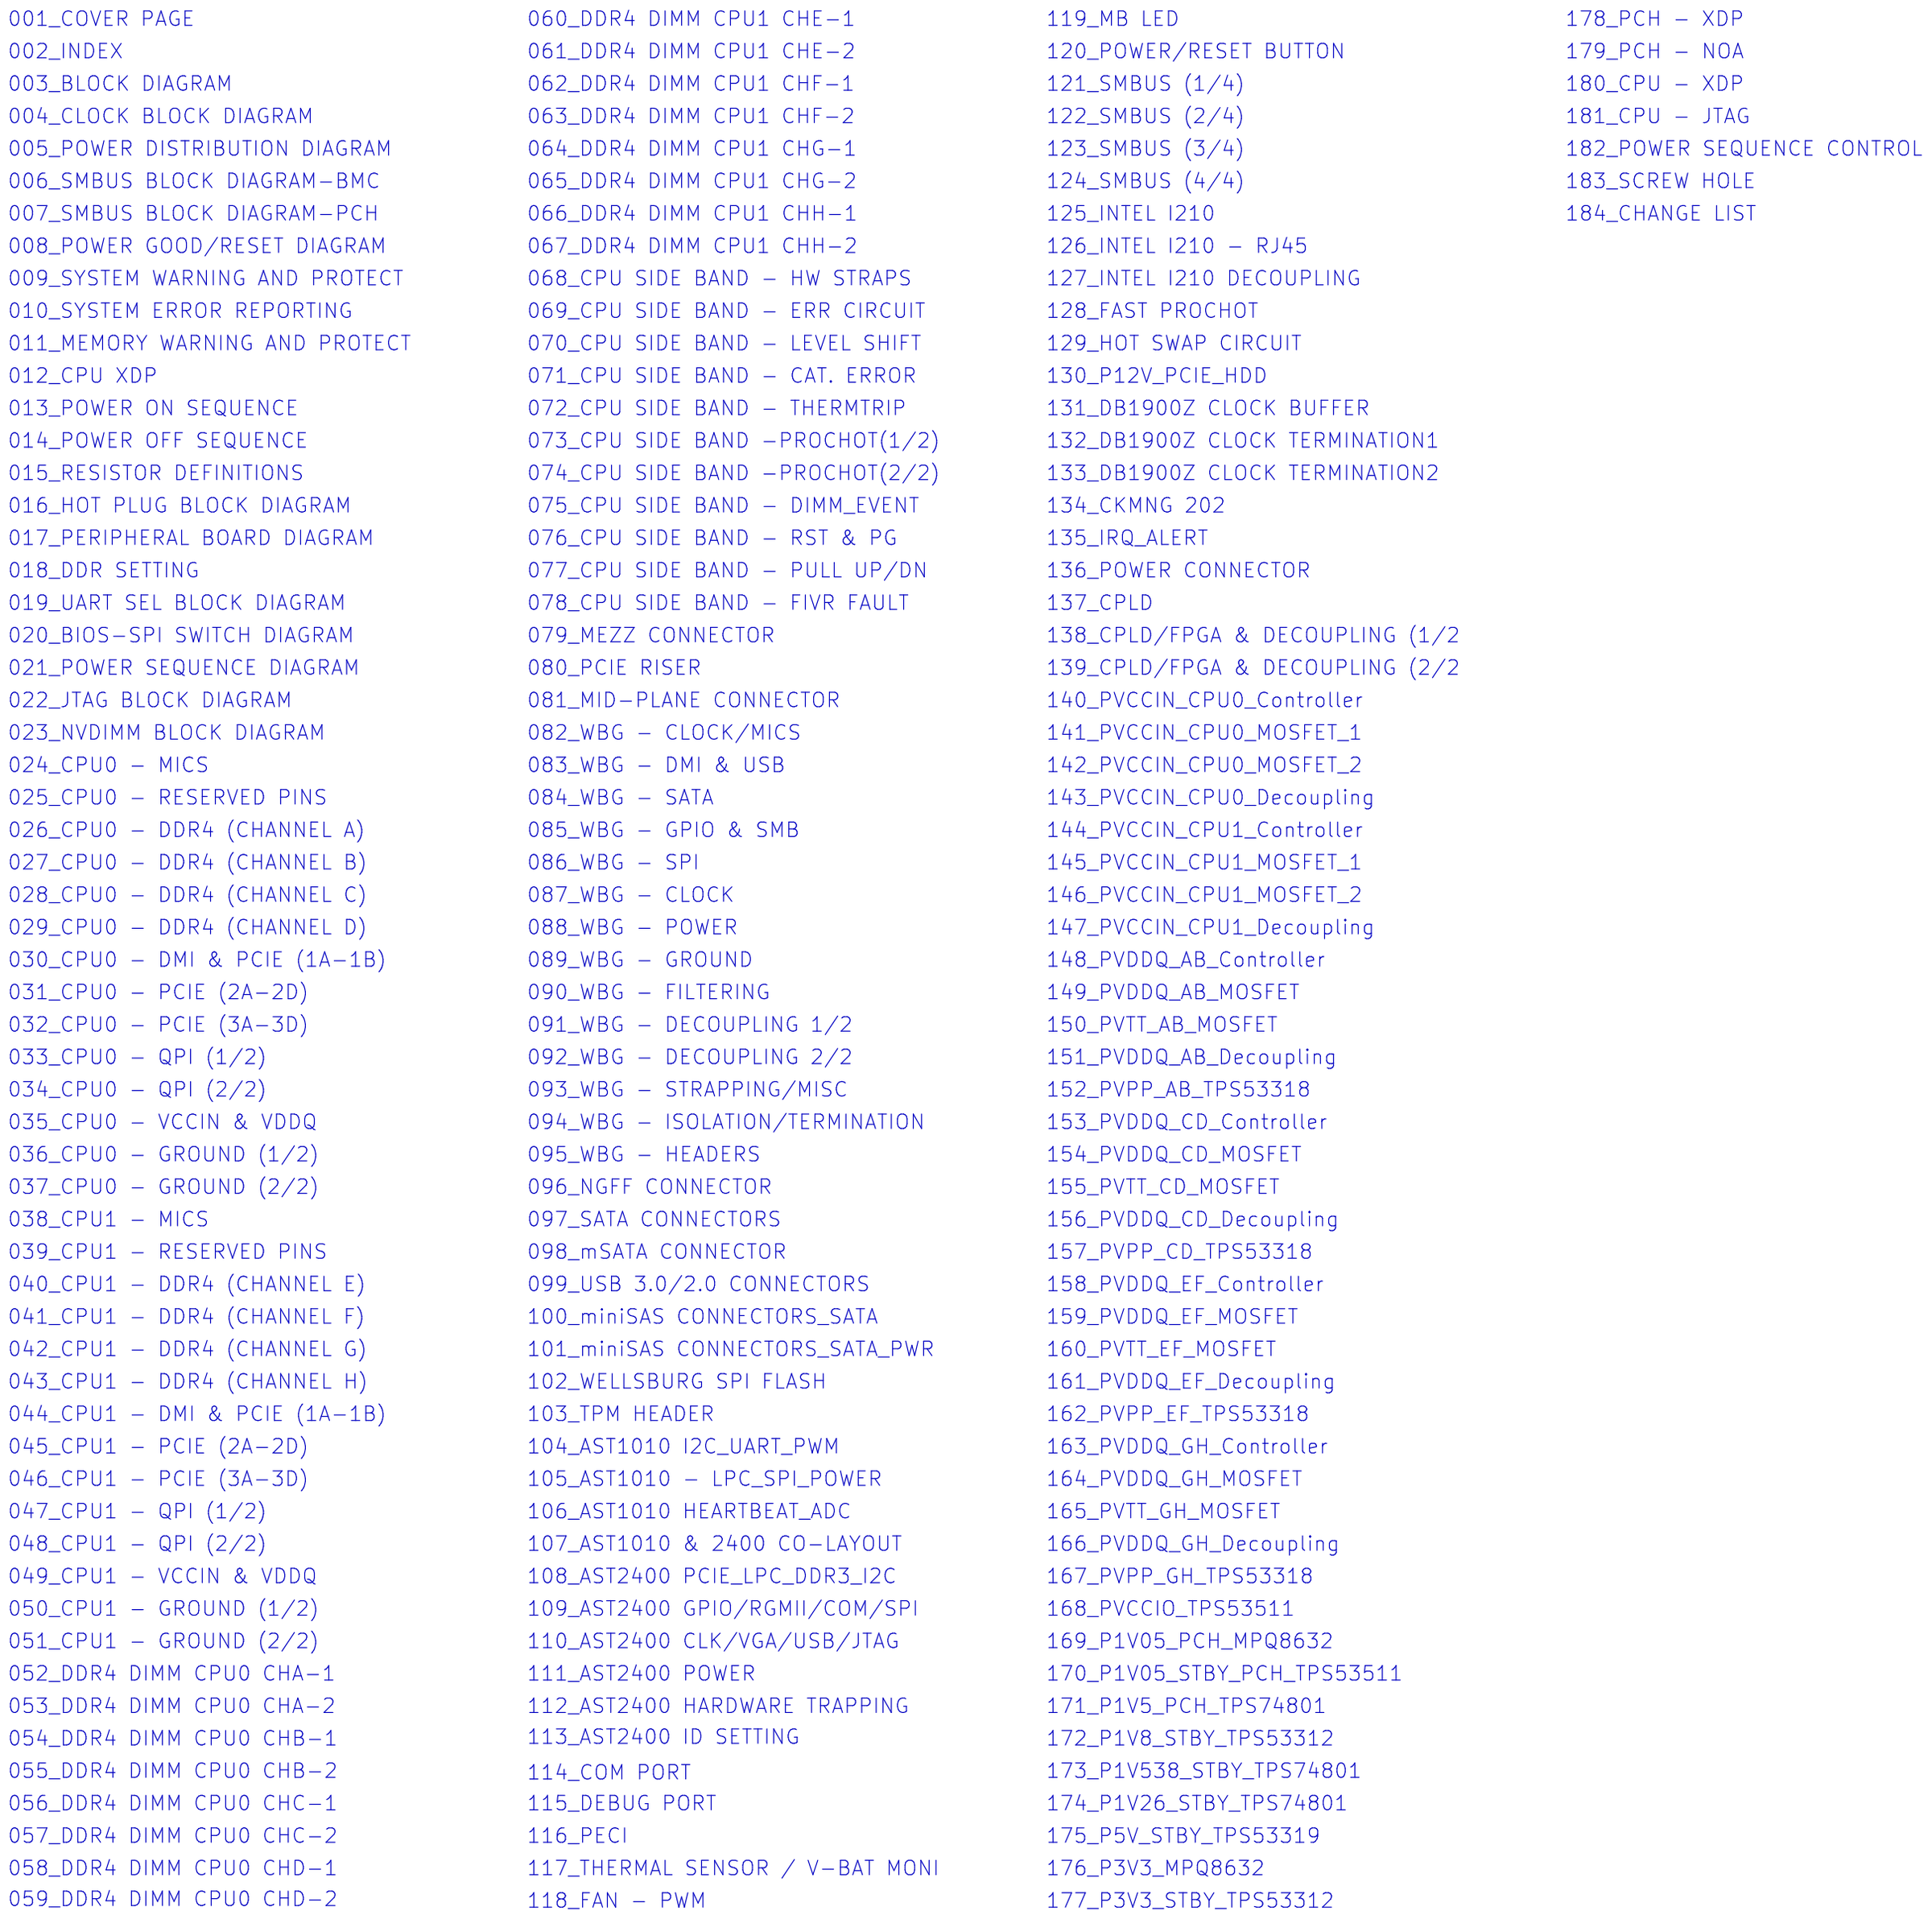
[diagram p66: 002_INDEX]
158 001_COVER PAGE: title: COVER PAGE
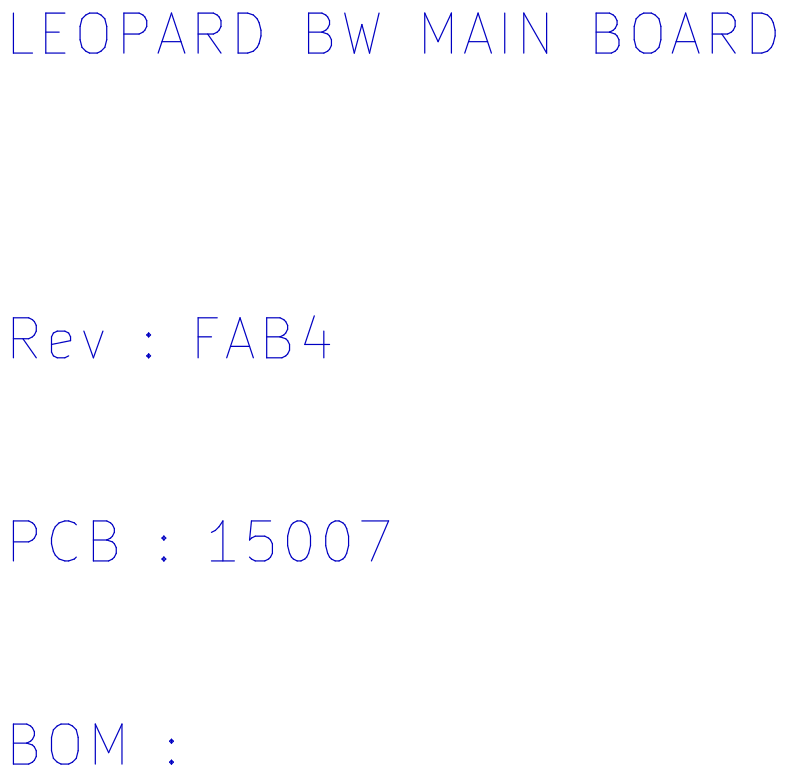
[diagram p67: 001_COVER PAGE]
159 123_SMBUS (3/4): size A3; title: SMBUS (3/4)
160 121_SMBUS (1/4): size A3; title: SMBUS (1/4)

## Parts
sheet 121_SMBUS (1/4)
C496  SCD1U16V2KX-3GP  [C402H22]
C497  SCD1U16V2KX-3GP  [C402H22]
C498  SCD1U16V2KX-3GP  [C402H22]
C499  SCD1U16V2KX-3GP  [C402H22]
C500  SCD1U16V2KX-3GP  [C402H22]
C501  SCD1U16V2KX-3GP  [C402H22]
C502  SCD1U16V2KX-3GP  [C402H22]
C503  SCD1U16V2KX-3GP  [C402H22]
R567  240R2F-1-GP  [R402H16]
R568  240R2F-1-GP  [R402H16]
R569  1KR2F-3-GP  [R402H16]
R570  1KR2F-3-GP  [R402H16]
R571  10KR2F-2-GP  [R402H16]
R572  10R2F-L-GP  [R402H14]
R573  10R2F-L-GP  [R402H14]
R574  1KR2F-3-GP  [R402H16]
R579  240R2F-1-GP  [R402H16]
R580  240R2F-1-GP  [R402H16]
R581  1KR2F-3-GP  [R402H16]
R582  1KR2F-3-GP  [R402H16]
R583  10KR2F-2-GP  [R402H16]
R584  1KR2F-3-GP  [R402H16]
R585  10R2F-L-GP  [R402H14]
R586  1KR2F-3-GP  [R402H16]
R587  1KR2F-3-GP  [R402H16]
R588  10R2F-L-GP  [R402H14]
R596  240R2F-1-GP  [R402H16]
R597  240R2F-1-GP  [R402H16]
R600  10KR2F-2-GP  [R402H16]
R602  10R2F-L-GP  [R402H14]
R603  10R2F-L-GP  [R402H14]
R604  240R2F-1-GP  [R402H16]
R605  240R2F-1-GP  [R402H16]
R608  10KR2F-2-GP  [R402H16]
R609  10R2F-L-GP  [R402H14]
R610  10R2F-L-GP  [R402H14]
U36  PCA9617ADP-GP  [MSOP8-1H44]
U37  PCA9617ADP-GP  [MSOP8-1H44]
U38  PCA9617ADP-GP  [MSOP8-1H44]
U39  PCA9617ADP-GP  [MSOP8-1H44]
sheet 123_SMBUS (3/4)
C97  SC1U10V2KX-4-GP  [C402H22]
R634  4K7R2F-GP  [R402H16]
R635  4K7R2F-GP  [R402H16]
R636  4K7R2F-GP  [R402H16]
R637  4K7R2F-GP  [R402H16]
R638  100R2F-L1-GP-U  [R402H14]
R639  100R2F-L1-GP-U  [R402H14]
R640  100R2F-L1-GP-U  [R402H14]
R641  100R2F-L1-GP-U  [R402H14]
U45  CAT24C64WI-GT3-GP  [SOIC8H69]

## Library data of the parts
C496-C503 = SCD1U16V2KX-3GP: CHIP CAP C 0.1U 16V K0402 X7R; CATEGORIES: CAP_1.xV; GREENDFACTOR: R2_SA;HF_SA;G_SA;; MAIN_SOURCE: M; Part Number: 78.10421.2FL; Part Type: SMD-BCG; SPEC: http://wpqssvr.wistron.com.tw:7001/wpqs/servlet/COM.qpart.Attachment?PartNumber=78.10421.2FL
R567 R568 R579 R580 R596 R597 R604 R605 = 240R2F-1-GP: CHIP RES 240 F 1/16W 0402(ROHS; Category: MSIC; DESCRIPTIO: CHIP RES 240 F 1/16W 0402(ROHS; GREENDFACTOR: R2_SA;HF_SA;G_SA;; Package Type: SMD-RG; Part Number: 64.24005.6DL; Part Type: SMD-RG; SPEC: http://wpqssvr.wistron.com.tw:7001/wpqs/servlet/COM.qpart.Attachment?PartNumber=64.24005.6DL; VENDORPARTNUMBER: RM04FTN2400 / RTT022400FTH / RR0510S-241-FN / RC0402FR-07240RL
R569 R570 R574 R581 R582 R584 R586 R587 = 1KR2F-3-GP: CHIP RES 1K F 1/16W 0402; GREENDFACTOR: R2_SA;HF_SA;G_SA;; Package Type: SMD-RG; Part Number: 64.10015.6DL; SPEC: http://wpqssvr.wistron.com.tw:7001/wpqs/servlet/COM.qpart.Attachment?PartNumber=64.10015.6DL
R571 R583 R600 R608 = 10KR2F-2-GP: CHIP RES 10K F 1/16W 0402; Category: MSIC; DESCRIPTIO: CHIP RES 10K F 1/16W 0402; GREENDFACTOR: R2_SA;HF_SA;G_SA;; POP?: NOPOP; Package Type: SMD-RG; Part Number: 64.10025.6DL; Part Type: SMD-RG; SPEC: http://wpqssvr.wistron.com.tw:7001/wpqs/servlet/COM.qpart.Attachment?PartNumber=64.10025.6DL; VENDORPARTNUMBER: RM04FTN1002 / RTT021002FTH / RR0510S-103-FN / RC0402FR-0710KL/WR04X1002FTL
R572 R573 R585 R588 R602 R603 R609 R610 = 10R2F-L-GP: CHIP RES 10 F 1/16W 0402; Category: BMC; DESCRIPTIO: CHIP RES 10 F 1/16W 0402; GREENDFACTOR: R2_SA;HF_SA;G_SA;; Package Type: SMD-RG; Part Number: 64.10R05.6DL; Part Type: SMD-RG; SPEC: http://wpqssvr.wistron.com.tw:7001/wpqs/servlet/COM.qpart.Attachment?PartNumber=64.10R05.6DL; VENDORPARTNUMBER: RM04FTN10R0 / RTT0210R0FTH / RR0510S-100-FN / RC0402FR-0710RL
U36-U39 = PCA9617ADP-GP: IC REPEATER PCA9617ADPJ TSSOP 8P; GREENDFACTOR: R2_SA;; Part Number: 71.09617.A0W; Part Type: DISCRET-G8; SPEC: http://wpqssvr.wistron.com.tw:7001/wpqs/servlet/COM.qpart.Attachment?PartNumber=71.09617.A0W
C97 = SC1U10V2KX-4-GP: CHIP CAP C 1U 10V K 0402 X6S; GREENDFACTOR: R2_SA;HF_SA;; Part Number: 78.10523.8FL; Part Type: SMD-BCG6; SPEC: http://wpqssvr.wistron.com.tw:7001/wpqs/servlet/COM.qpart.Attachment?PartNumber=78.10523.8FL
R634 R635 = 4K7R2F-GP: CHIP RES 4.7K F 1/16W 0402; Category: LOM - i350; DESCRIPTIO: CHIP RES 4.7K F 1/16W 0402; GREENDFACTOR: R2_SA;HF_SA;G_SA;; Package Type: RCL_GP; Part Number: 64.47015.6DL; Part Type: RCL_GP; SPEC: http://wpqssvr.wistron.com.tw:7001/wpqs/servlet/COM.qpart.Attachment?PartNumber=64.47015.6DL; VENDORPARTNUMBER: RM04FTN4701/RTT024701FTH/RR0510S-472-FN/RC0402FR-074K7L/WR04X4701FTL
R636 R637 = 4K7R2F-GP: CHIP RES 4.7K F 1/16W 0402; Category: LOM - i350; DESCRIPTIO: CHIP RES 4.7K F 1/16W 0402; GREENDFACTOR: R2_SA;HF_SA;G_SA;; POP?: NOPOP; Package Type: RCL_GP; Part Number: 64.47015.6DL; Part Type: RCL_GP; SPEC: http://wpqssvr.wistron.com.tw:7001/wpqs/servlet/COM.qpart.Attachment?PartNumber=64.47015.6DL; VENDORPARTNUMBER: RM04FTN4701/RTT024701FTH/RR0510S-472-FN/RC0402FR-074K7L/WR04X4701FTL
R638 R639 = 100R2F-L1-GP-U: CHIP RES 100 F 1/16W 0402; Category: PSU conn; GREENDFACTOR: R2_SA;HF_SA;G_SA;; POP?: NOPOP; Package Type: SMD-RG; Part Number: 64.10005.6DL; Part Type: SMD-RG; SPEC: http://wpqssvr.wistron.com.tw:7001/wpqs/servlet/COM.qpart.Attachment?PartNumber=64.10005.6DL; VENDORPARTNUMBER: RM04FTN1000 / RTT021000FTH / RR0510S-1000-FN / RC0402FR-07100RL/WR04X1000FTL
R640 R641 = 100R2F-L1-GP-U: CHIP RES 100 F 1/16W 0402; Category: PSU conn; GREENDFACTOR: R2_SA;HF_SA;G_SA;; Package Type: SMD-RG; Part Number: 64.10005.6DL; Part Type: SMD-RG; SPEC: http://wpqssvr.wistron.com.tw:7001/wpqs/servlet/COM.qpart.Attachment?PartNumber=64.10005.6DL; VENDORPARTNUMBER: RM04FTN1000 / RTT021000FTH / RR0510S-1000-FN / RC0402FR-07100RL/WR04X1000FTL
U45 = CAT24C64WI-GT3-GP: IC EEPROM CAT24C64WI-GT3 SOIC 8P; GREENDFACTOR: R2_SA;G_SA;; Part Number: 72.24C64.I01; Part Type: MEMORY-G4; SPEC: http://wpqssvr.wistron.com.tw:7001/wpqs/servlet/COM.qpart.Attachment?PartNumber=72.24C64.I01

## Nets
GND: C97.2 C496.2 C497.2 C498.2 C499.2 C500.2 C501.2 C502.2 C503.2 R638.2 R639.2 R640.2 R641.2 U36.4(GND) U37.4(GND) U38.4(GND) U39.4(GND) U45.4(VSS) ; also on sheet 1 2 3 4 5 6 7 8 9 10 11 12 13 14 15 16 17 18 19 20 21 22 23 24 25 26 27 28 29 30 31 32 33 34 35 36 37 38 39 44 46 47 49 50 51 52 53 54 55 56 57 58 59 60 61 62 63 64 65 66 69 70 71 73 74 75 76 78 79 80 81 82 83 84 86 87 88 89 90 91 92 93 94 95 96 97 98 99 100 101 102 103 104 105 106 107 108 109 110 111 112 113 114 115 116 117 118 119 128 129 138 139 161 166 168 169 170 171 172 173 174 175 176 177 180 181 182 183 184
P3V3_STBY: C97.1 R634.1 R635.1 R636.1 R637.1 U45.8(VCC) ; also on sheet 2 3 5 6 8 9 10 11 12 15 16 17 20 21 22 25 26 27 30 31 33 34 35 37 38 39 45 47 49 50 51 52 54 55 59 60 61 62 63 64 65 66 69 70 71 72 73 74 76 79 83 84 87 88 89 90 91 92 93 94 95 96 97 98 99 161 166 168 173 174 176 177 179 180 182 183 184
PVCCIO: C496.1 C498.1 C500.1 C502.1 R567.1 R568.1 R579.1 R580.1 R596.1 R597.1 R604.1 R605.1 U36.1(VCCA) U37.1(VCCA) U38.1(VCCA) U39.1(VCCA) ; also on sheet 11 16 26 35 39 46 47 68 87 97 100 101 102 103 120 129 130 139 173 177 179 182
PD_PV_TRKG_FRU_A2: R636.2 R640.1 U45.3(A2)
PD_PV_TRKG_FRU_WP: R637.2 R641.1 U45.7(WP)
PU_PV_TRKG_FRU_A0: R634.2 R638.1 U45.1(A0)
PU_PV_TRKG_FRU_A1: R635.2 R639.1 U45.2(A1)
PU_SMB_DDR_AB_VT_EN: R571.2 U36.5(EN)
PU_SMB_DDR_CD_VT_EN: R583.2 U37.5(EN)
PU_SMB_DDR_EF_VT_EN: R600.2 U38.5(EN)
PU_SMB_DDR_GH_VT_EN: R608.2 U39.5(EN)
PVPP_AB: C497.1 R569.2 R570.2 R571.1 U36.8(VCCB) ; also on sheet 27 98 116 117 118 119
PVPP_CD: C499.1 R574.2 R581.2 R583.1 U37.8(VCCB) ; also on sheet 22 112 113 114 115
PVPP_EF: C501.1 R582.2 R584.2 R600.1 U38.8(VCCB) ; also on sheet 17 108 109 110 111
PVPP_GH: C503.1 R586.2 R587.2 R608.1 U39.8(VCCB) ; also on sheet 12 104 105 106 107
SMB_DDR_AB_SCL_G: R572.1 ; also on sheet 139
SMB_DDR_AB_SCL_LVC2V5: R569.1 U36.7(SCLB) ; also on sheet 116 117 118 119
SMB_DDR_AB_SCL_R: R567.2 R572.2 U36.2(SCLA)
SMB_DDR_AB_SDA_G: R573.1 ; also on sheet 139
SMB_DDR_AB_SDA_LVC2V5: R570.1 U36.6(SDAB) ; also on sheet 116 117 118 119
SMB_DDR_AB_SDA_R: R568.2 R573.2 U36.3(SDAA)
SMB_DDR_CD_SCL_G: R585.1 ; also on sheet 139
SMB_DDR_CD_SCL_LVC2V5: R574.1 U37.7(SCLB) ; also on sheet 112 113 114 115
SMB_DDR_CD_SCL_R: R579.2 R585.2 U37.2(SCLA)
SMB_DDR_CD_SDA_G: R588.1 ; also on sheet 139
SMB_DDR_CD_SDA_LVC2V5: R581.1 U37.6(SDAB) ; also on sheet 112 113 114 115
SMB_DDR_CD_SDA_R: R580.2 R588.2 U37.3(SDAA)
SMB_DDR_EF_SCL_G: R602.1 ; also on sheet 129
SMB_DDR_EF_SCL_LVC2V5: R582.1 U38.7(SCLB) ; also on sheet 108 109 110 111
SMB_DDR_EF_SCL_R: R596.2 R602.2 U38.2(SCLA)
SMB_DDR_EF_SDA_G: R603.1 ; also on sheet 129
SMB_DDR_EF_SDA_LVC2V5: R584.1 U38.6(SDAB) ; also on sheet 108 109 110 111
SMB_DDR_EF_SDA_R: R597.2 R603.2 U38.3(SDAA)
SMB_DDR_GH_SCL_G: R609.1 ; also on sheet 129
SMB_DDR_GH_SCL_LVC2V5: R586.1 U39.7(SCLB) ; also on sheet 104 105 106 107
SMB_DDR_GH_SCL_R: R604.2 R609.2 U39.2(SCLA)
SMB_DDR_GH_SDA_G: R610.1 ; also on sheet 129
SMB_DDR_GH_SDA_LVC2V5: R587.1 U39.6(SDAB) ; also on sheet 104 105 106 107
SMB_DDR_GH_SDA_R: R605.2 R610.2 U39.3(SDAA)
SMB_SENSOR_CLK: U45.6(SCL) ; also on sheet 52 74 184
SMB_SENSOR_DAT: U45.5(SDA) ; also on sheet 52 74 184

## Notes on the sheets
sheet 149
- POWER OFF SEQUENCE
- >50 us
- >11 us
- >30 us
- RST_PLTRST_N
- PWRGD_CPUPWRGD_1V
- FM_SLPS3_N
- FM_SLPA_N
- FM_PS_EN
- PWRGD_PS_PWROK
- P12V_PCIE_HDD
- P5V
- P3V3
- P1V5_PCH
- P1V05_PCH
- PVCCIN_CPU0/1
- PVCCIO
- >30 us
- FM_SLPS4_N
- PVPP_AB/CD/EF/GH
- PVDDQ_AB/CD/EF/GH
- PWRGD_PVPP_PVDDQ_AB/CD/EF/GH
- PWRGD_SYS_PWROK
- PWRGD_PCH_PWROK
- P12V_STBY
- P5V_STBY
- P3V3_STBY
- P1V8_STBY
- RST_RTCRST_N
- P3V3_BAT
sheet 150
- POWER ON SEQUENCE
- AC Plug-In
- P3V_BAT
- RST_RTCRST_N
- MB_MATED_N(Mid-plane)
- PWR_AUX_EN
- P12V_MAIN
- P12V_STBY
- P5V_STBY
- P3V3_STBY
- P1V8_STBY
- RST_RSMRST_PCH_N
- TP_SLPSUS_N_BUFF
- FM_SLPA_N
- P1V05_STBY_PCH
- PWRGD_PCH_APWROK
- PWRBTN#
- FM_SLPS4_N
- FM_SLPS3_N
- FM_PS_EN
- P12V_PCIE_HDD
- PWRGD_PS_PWROK
- P5V
- P1V05_PCH
- PVCCIO
- P3V3
- P1V5_PCH
- PVPP_AB/CD/EF/GH
- PVDDQ_AB/CD/EF/GH
- PWRGD_PVPP_PVDDQ_AB/CD/EF/GH
- PVTT_AB/CD/EF/GH
- PVCCIN_CPU0/1_EN
- PVCCIN_CPU0/1
- PWRGD_PVCCIN_CPU0/1
- PWRGD_PCH_PWROK
- PWRGD_SYS_PWROK
- PWRGD_DRAMPWRGD_CO
- PWRGD_CPUPWRGD_1V
- RST_PLTRST_N
sheet 151
- PVCCIO
- PVCCIO
- PVCCIO
- PVCCIO
- CPU XDP
- R702
- R1245
- R1246
- R1247
- 100ohm
- 100ohm
- 100ohm
- 100ohm
- PVCCIO
- OBSDATA_A[0:3]
- OBSFN_B[0:1]
- R995 and R996
- 100ohm
- OBSDATA_B[0:3]
- U146
- XDP_CPU1_PREQ_G_N
- BI[3]
- BO[3]
- OBSFN_A0
- XDP_CPU0_PREQ_G_N
- XDP_CPU1_PRDY_G_N
- (PREQ)
- BO[1]
- BI[1]
- XDP_CPU0_PRDY_G_N
- P.181
- OBSFN_A1
- (PRDY)
- PVCCIO
- PVCCIO
- 100ohm
- 100ohm
- PRDY_N
- PREQ_N
- BPM_[2:5]
- BPM_[6:7]
- PRDY_N
- PREQ_N
- BPM_[2:5]
- BPM_[6:7]
- CPU XDP
  Connector
- XDP_CPU0_SKTOCC_N
- R15
- R16
- PVCCIO
- BPM_0
- BPM_0
- R1001
- PVCCIO
- CPU1
- BPM_1
- 75ohm
- CPU0
- BPM_1
- R1000
- 75ohm
- 0
- TDI
- TDO
- XDP_CPU_TDI
- XDP_CPU0_TDI_G
- XDP_CPU0_TDO_G
- U72
- TDO
- TDI
- 1
- TDI
- U69
- XDP_CPU_EN
- TMS
- TRST_N
- TCK0
- TMS
- TRST_N
- TCK0
- XDP_CPU_TDO
- U71
- TDO
- P.25- 37
- P.38 - 61
- NAND
  Gate
- PVCCIO
- XDP_CPU1_SKTOCC_N
- XDP_CPU0_SKTOCC_N
- R611
- XDP_CPU1_TDI_G
- 49.9ohm
- TMS
- XDP_CPU_TMS_G
- XDP_CPU_TRST_G_N
- TRST_N
- TCK0
- R613
- 49.9ohm
- U70
- R612
- P.180
- 0
- XDP_CPU1_TDO_G
- 49.9ohm
- XDP_CPU0_TDO_G
- 1
- P.181
- XDP_CPU1_SKTOCC_N
sheet 152
- MEMORY WARNING AND PROTECT
- PVCCIO
- R84
  75£[
- R85
  75£[
- R86
  75£[
- R87
  75£[
- BMC
- U8
- R1129
- MEM_HOT_C1_N
- H_CPU0_MEMAB_MEMHOT_G_N
- H_CPU0_MEMAB_MEMHOT_LVT3_N
- 0£[
- H_CPU0_MEMAB_MEMHOT_BMC_LVT3_N
- GPIOM2
- CPU0
- H_CPU0_MEMCD_MEMHOT_G_N
- H_CPU0_MEMCD_MEMHOT_LVT3_N
- R1131
- H_CPU0_MEMCD_MEMHOT_BMC_LVT3_N
- MEM_HOT_C23_N
- Level Shift
- 0£[
- GPIOM3
- P.25- 37
- GTL2014PW
- MEM_HOT_C1_N
- H_CPU1_MEMEF_MEMHOT_G_N
- H_CPU1_MEMEF_MEMHOT_LVT3_N
- R1133
- 0£[
- H_CPU1_MEMEF_MEMHOT_BMC_LVT3_N
- GPIOM4
- CPU1
- R1135
- MEM_HOT_C23_N
- H_CPU1_MEMGH_MEMHOT_G_N
- H_CPU1_MEMGH_MEMHOT_LVT3_N
- 0£[
- H_CPU1_MEMGH_MEMHOT_BMC_LVT3_N
- GPIOM5
- P.70
- P.38 - 61
- U12/U14/U13/U15
- VR Hot from MEMAB
- IRQ_PVDDQ_AB_VRHOT_LVT3_N
- Buffer
- VR Hot from MEMCD
- IRQ_PVDDQ_CD_VRHOT_LVT3_N
- VR Hot from MEMEF
- IRQ_PVDDQ_EF_VRHOT_LVT3_N
- NTJD4001NT1G
- P3V3_STBY
- VR Hot from MEMGH
- IRQ_PVDDQ_GH_VRHOT_LVT3_N
- P.73
- PR1999
  1k£[
- PR2031
  1k£[
- PR2063
  1k£[
- PR2128
  1k£[
- GPION3
- GPION4
- GPIOO4
- GPIOO5
- P.108 - 110
sheet 153
- SYSTEM ERROR REPORTING
- P.25- 37
- PVCCIO
- CPU0
- H_CPU0_CATERR_G_N
- P.70
- CATERR_N
- R164
  150£[
- R166
  150£[
- U6
- BMC
- H_CPU_CATERR_G_N
- Level Shift
- FM_CPU_CATERR_LVT3_N
- FROM
  CPUs
- R961
- 0£[
- GPIOD2
- P.38 - 61
- R964
- 0£[
- VOLTAGE
  TRANSLATOR
  GTL TO LVT3
- GTL2014PW
- To BMC
- CPU1
- P.108 - 110
- P3V3
- H_CPU1_CATERR_G_N
- CATERR_N
- CATERR_N
  Delay Circuit
  to WBG
- R253
  4k7£[
- PCH
- IRQ_CPU_CATERR_DLY
- GPIO5
- TO WBG
- P.71
- P.82 - 93
- P.25- 37
- PVCCIO
- CPU0
- H_CPU0_FIVR_FAULT_G
- NOPOP
- NOPOP
- FIVR_FAULT
- R123
  1k£[
- R126
  1k£[
- U6/U7
- BMC
- Level Shift
- FM_CPU0_FIVR_FAULT_LVT3
- GPIOD0
- FM_CPU1_FIVR_FAULT_LVT3
- P.38 - 61
- GTL2014PW
- GPIOD1
- CPU1
- P.70
- H_CPU1_FIVR_FAULT_G
- P.108 - 110
- FIVR_FAULT
- PVCCIO
- P.25- 37
- CPU0
- P3V3
- P3V3_STBY
- P3V3
- R42
  75£[
- R43
  75£[
- R44
  75£[
- R197
  10k£[
- R552
  4k7£[
- R188
  10k£[
- U3
- PCH
- ERROR_N0
- H_CPU0_ERR0_G_N
- FM_CPU0_ERR0_LVT3_N
- U5A
- FM_CPU0_ERR0_LVT3_N_R
- R61
- 0£[
- FM_CPU_ERR0_CO_N
- TO PCH
- GPIO2
- correctable errors
- Level Shift
- CPLD1
- H_CPU0_ERR1_G_N
- FM_CPU0_ERR1_LVT3_N
- U5B
- FM_CPU0_ERR1_LVT3_N_R
- FM_CPU_ERR1_CO_N
- TO CPLD
- FM_ERR1_DLY_N
- ERROR_N1
- R62
- 0£[
- CPLD
- GPIO3
- Uncorrected but recoverable
  errors(non-fatal)
- GTL2014PW
- U5C
- TO BMC
- P.138
- ERROR_N2
- H_CPU0_ERR2_G_N
- FM_CPU0_ERR2_LVT3_N
- FM_CPU0_ERR2_LVT3_N_R
- R63
- 0£[
- CPU0_ERR2_N
- Uncorrected fatal error
- P.82 - 93
- P.69
- P.38 - 61
- PVCCIO
- CPU1
- P3V3_STBY
- R52
  75£[
- R53
  75£[
- R54
  75£[
- U4
- U5D
- ERROR_N0
- H_CPU1_ERR0_G_N
- FM_CPU1_ERR0_LVT3_N
- FM_CPU1_ERR0_LVT3_N_R
- R64
- 0£[
- R142
  4k7£[
- R143
  4k7£[
- Level Shift
- BMC
- ERROR_N1
- H_CPU1_ERR1_G_N
- FM_CPU1_ERR1_LVT3_N
- U5E
- FM_CPU1_ERR1_LVT3_N_R
- R65
- 0£[
- GPIOJ6
- GTL2014PW
- H_CPU1_ERR2_G_N
- FM_CPU1_ERR2_LVT3_N
- U5F
- FM_CPU1_ERR2_LVT3_N_R
- CPU1_ERR2_N
- TO BMC
- ERROR_N2
- R66
- 0£[
- GPIOJ7
- Uncorrected fatal error
- P.69
- P.108 - 110
sheet 154
- SYSTEM WARNING AND PROTECT
- PVPP_AB
- P3V3_STBY
- P.75
- P.108 - 110
- DIMM CHA EVENT
- FM_CPU_DIMM_EVENT_CO_N
- R1096
  2k21£[
- U31
- R1095
  4k7£[
- BMC
- Level Shift
- FM_MEM_THERM_EVENT_LVT3_N
- GPIOQ6
- DIMM CHB ~ CHH EVENT
- NTJD4001NT1G
- P.82 - 93
- CPU0A
- PVCCIO
- PVCCIO
- U97C
- P3V3_STBY
- PVCCIO
- PCH
- CPU0
- P.138
- P.94
- H_CPU0_THERMTRIP_G_N
- R122
  75£[
- R125
  75£[
- P.70
- R553
  10k£[
- CPLD1
- Q10
- R232
  200£[
- U6/U7
- THERMTRIP_N
- FM_CPU0_THERMTRIP_LVT3_N
- U97A
- CPLD
- FM_LVC3_THERMTRIP_DLY
- Level Shift
- FM_LVC1_THERMTRIP_N
- Level Shift
- (INVERT)
- THRMTRIP_N
- P.25 - 37
- FM_THERMTRIP_CO_N
- LMBT3904LT1G
- P3V3
- CPU1A
- GTL2014PW
- FM_CPU1_THERMTRIP_LVT3_N
- U97B
- U97E
- CPU1
- R195
  10k£[
- H_CPU1_THERMTRIP_G_N
- FM_CPU_PROCHOT_N
- R971
- 0£[
- NOA_13_FM_CPU_PROCHOT_N
- GPIO49
- THERMTRIP_N
- U97F
- P3V3_STBY
- P.38 - 61
- PVCCIO
- PVCCIO
- P.108 - 110
- R198
  10k£[
- P.70
- BMC
- R69
  75£[
- R76
  75£[
- U6/U7
- NOPOP
- R1116
  0£[
- R1117
  0£[
- FM_PCH_BMC_THERMTRIP_R_N
- NOPOP
- GPIO74
- CPU0 and CPU1
- H_CPU0_PROCHOT_G_N
- Level Shift
- FM_CPU0_PROCHOT_LVT3_N
- GPIOM6_TXD2_VPIB8
- R1114
  0£[
- FM_CPLD_BMC_THERMTRIP_N
- PROCHOT_N
- H_CPU1_PROCHOT_G_N
- GTL2014PW
- FM_CPU1_PROCHOT_LVT3_N
- GPIOF0_NCTS4
- P.137
- GPIOM7_RXD2_VPIB9
- CPLD2
- GPIOL1
- P3V3
- P3V3
- CPLD
- CPLD1
- P.73
- R94
  4k7£[
- R95
  4k7£[
- P.73
- P.74
- CPLD
- U11
- U9/U10
- U93
- IRQ_CPU0_VRHOT_D
- H_CPU0_PROCHOT_G_N
- Gate
- Level Shift
- Level Shift
- P.138
- FM_SYS_THROTTLE_LVC3_N
- H_CPU1_PROCHOT_G_N
- RST_DLY_CPURST_LVC3
- NTJD4001NT1G
- IRQ_CPU1_VRHOT_D
- NTJD4001NT1G
- NTJD4001NT1G
- PU1/PU7
- P.108 - 110
- BMC
- P3V3_STBY
- P3V3
- IRQ_PVCCIN_CPU0_VRHOT_LVT3_N
- PVCCIN_CPU0 and
  PVCCIN_CPU1
- GPIOO6
- P3V3
- R1039
  10k£[
- R1210
  10k£[
- P.74
- U96
- IRQ_PVCCIN_CPU1_VRHOT_LVT3_N
- FM_THROTTLE_N_BMC
- R985
  10k£[
- P.74
- VR_HOT_N
- GPIOO7
- GPIOD3
- AND GATE
- U91
- U92
- P.74
- FM_THROTTLE_N
- AND GATE
- PCH
- SN74LVC1G08
- FM_THROTTLE_AND_N
- NOR gate
- GPIO16
- NOA_12_FM_NM_THROTTLE_N
- SN74LVC1G08
- RST_PLTRST_DLY
- P3V3_STBY
- 74LVC1G02
- FAST PROCHOT
  CURRENT MODE
- P.82 - 93
- P3V3_STBY
- R1591
  10k£[
- R1590
  10k£[
- IRQ_SML1_PMBUS_ALERT_BUF_N
- P.128
- CURRENT_ALERT_N
- CPLD2
- CURRENT_ALERT_CPLD_OUT
- R647
- 0£[
- R668
  10k£[
- CPLD1
- FAST PROCHOT
  VOLTAGE MODE
- VOLTAGE_ALERT_N
- CPLD
- VOLTAGE_ALERT_CPLD_OUT
- R462
- 0£[
- IRQ_SML1_PMBUS_ALERT_BUF_N
- CPLD
- PMBUS_ALERT_CPLD_OUT
- P3V3_STBY
- R688
- 0£[
- P.128
- P.137
- R2096
  4k7£[
- P.82 - 93
- P.138
- U2
- PCH
- HSC
- MB0_CURMON_ALERT1_R_N
- R148
- 0£[
- IRQ_SML1_PMBUS_ALERT_N
- GPIO31
- P.129
- P5V_STBY
- P.81
- P.108 - 110
- MIDCN2
- R199
  10k£[
- BMC
- MID-PLANE
  CONNECTOR
- IRQ_MID_PMBUS_ALERT_N
- Level Shift
- IRQ_SML1_PMBUS_ALERT_N
- GPIOB1_SALT2
sheet 155
- POWER DISTRIBUTION DIAGRAM
- Switch VR
- Linear VR
- P.168
- TPS53312RGTR
- PVCCIO (TDC: 0.5A Max: 1A)
- 0R
- CPU0
- CPU1
- PSU_12V
- P.140
- PCH
  WELLSBURG
- HOT SWAP
  CONTROLLER
  ADM1276
- P12V_STBY
- PX3746DQ
  5 Phase
- PVCCIN_CPU0
- CPU0 (TDC: 103A Max:190A)
- BMC
  AST1010A0
- P.144
- P.169
- PX3746DQ
  5 Phase
- PVCCIN_CPU1
- CPU1 (TDC: 103A Max:190A)
- TPS53318DQPR
- P1V05_PCH (TDC: 6A Max: 6.7A)
- PCH
  WELLSBURG
- P.129
- P.170
- TPS53312RGTR
- P1V05_STBY_PCH (TDC: 0.6A Max: 1A)
- PCH
  WELLSBURG
- P12V_STBY
- 0R
- P.171
- P1V5_PCH (TDC: 2.2A Max: 2.2A)
- TPS74801
- PCH
  WELLSBURG
- 0R
- P.148
- P.172
- PX3244DQ-GP
  2 Phase
- PVDDQ_AB (TDC: 45A Max: 80A)
- TPS53312RGTR
- P1V8_STBY (TDC: 1.45A Max: 1.96A)
- BMC
  AST1250
- 0R
- P.153
- P.173
- PVDDQ_CD (TDC: 45A Max: 80A)
- BMC
  AST1250
- PX3244DQ-GP
  2 Phase
- TPS74801
- P1V538_STBY (TDC:0.4A Max:0.5A)
- P.150
- PVTT_AB (TDC:3A Max: 3.6A)
- P.174
- PX3517-GP
  1 Phase
- DDR4
  CH-ABCD
- BMC
  AST1250
- P.155
- TPS74801
- P1V26_STBY (TDC:0.7A Max:0.76A)
- PX3517-GP
  1 Phase
- PVTT_CD (TDC:3A Max: 3.6A)
- P.175
- TPS54620RGY
- P5V_STBY (TDC: 2.75A Max: 3.44A)
- P.152
- MEZZ Conn
- TPS53318DQPR
  1 Phase
- PVPP_AB (TDC: 3.24A Max: 6.6A)
- P5V
- P.157
- MOSFET
- USB
- TPS53318DQPR
  1 Phase
- PVPP_CD (TDC: 3.24A Max: 6.6A)
- HDD
- P.158
- P.176
- PVDDQ_EF (TDC: 45A Max: 80A)
- PX3244DQ-GP
  2 Phase
- TPS53319DQPR
- P3V3 (TDC: 10.4A Max: 10.4A)
- PCH
  WELLSBURG
- P.163
- PVDDQ_GH (TDC: 45A Max: 80A)
- PX3244DQ-GP
  2 Phase
- P.177
- MEZZ Conn
- P.160
- P3V3_STBY
  (TDC: 1.95A Max: 1.95A)
- PX3517-GP
  1 Phase
- PVTT_EF (TDC:3A Max: 3.6A)
- DDR4
  CH-EFGH
- PCIE RISER
- TPS53312RGTR
- PCH
  WELLSBURG
- P.82 - 93
- P.165
- 0R
- mSATA Conn
- PVTT_GH (TDC:3A Max: 3.6A)
- BMC
  AST2400
- P.108 - 110
- PX3517-GP
  1 Phase
- P.162
- DB1900Z
- PVPP_EF (TDC: 3.24A Max: 6.6A)
- MEZZ Conn
- TPS53318DQPR
  1 Phase
- MOSFET
- P.79
- P.167
- PCIE RISER
- P.80
- TPS53318DQPR
  1 Phase
- PVPP_GH (TDC: 3.24A Max: 6.6A)
- SASPW1
- Springville
  (INTEL I210)
- P12V_PCIE_HDD
- P.125- 127
- HDPR1
- P.134
- CKMNG
- CPLD
- P.138
- mSATA
- P.98
- P.96
- NGFF
sheet 156
- Leopard BDW-EP Block Diagram
- DDR4
  (288 pins)
- DIMM
- DIMM
- DIMM
- DIMM
- DIMM
- DIMM
- DIMM
- DIMM
- DDR4
  (288 pins)
- QPI Port0
- CPU0
  Broadwell EP
- CPU1
  Broadwell EP
- 9.6GT/s
- P.52- 59
- P.60- 67
- QPI Port1
- DIMM
- DIMM
- DIMM
- DIMM
- DIMM
- DIMM
- DIMM
- DIMM
- 9.6GT/s
- P.25- 37
- P.38 - 61
- Port 1A x8 PCIe
- PECI
- X4 DMI2
- PCIe x24 slot
- Port 2A x16 PCIe
- P.80
- Port 3C x8 PCIe
- PCIe x8 Mezzanine card slot
- P.79
- Port 3A x8 PCIe
- MIDPLANE connector
- P.81
- SGMII/KX
- RJ45
- P.99
- USB 3.0/2.0 Internal
- P.126
- 10/100/1000
  MDI
- P.99
- USB 3.0/2.0 External
- SATA4
- x1 PCIe
- P.99
- mSATA CONN
- I210
- WellsBurg
- SATA5
- P.97
- SATA CONN
- x4 PCIe
- NGFF CONN
- P.125- 127
- SSATA0~3
- miniSAS Vertical x4 port0
- P.96
- SATA0~3
- miniSAS Vertical x4 port1
- Midplane UART
- P.82 - 93
- P.100
- SML0
- LPC
- SPI
- UART Channel SEL
- SML1
- BMC debug UART
- UART
  switch
- Host UART
- P.115
- PMBus
- Debug
  header
- HSC
- BMC
- PORT 80 LED
- P.114
- P.129
- Management I2C
- AST1250 (2400)
- Management RMII
- FAN PWM
- I2C
- FAN
  CONN*2
- Sensors
- FAN TACH
- P.117
- P.108 - 110
- BMC FW
  SPI Flash
- MUX
- P.102
- P.109
- Primary
- BIOS
  SPI Flash
  backup
- BIOS
- flash
sheet 157
- 001_COVER PAGE
- 060_DDR4 DIMM CPU1 CHE-1
- 119_MB LED
- 178_PCH - XDP
- 002_INDEX
- 061_DDR4 DIMM CPU1 CHE-2
- 120_POWER/RESET BUTTON
- 179_PCH - NOA
- 003_BLOCK DIAGRAM
- 062_DDR4 DIMM CPU1 CHF-1
- 121_SMBUS (1/4)
- 180_CPU - XDP
- 004_CLOCK BLOCK DIAGRAM
- 063_DDR4 DIMM CPU1 CHF-2
- 122_SMBUS (2/4)
- 181_CPU - JTAG
- 005_POWER DISTRIBUTION DIAGRAM
- 064_DDR4 DIMM CPU1 CHG-1
- 123_SMBUS (3/4)
- 182_POWER SEQUENCE CONTROL
- 006_SMBUS BLOCK DIAGRAM-BMC
- 065_DDR4 DIMM CPU1 CHG-2
- 124_SMBUS (4/4)
- 183_SCREW HOLE
- 007_SMBUS BLOCK DIAGRAM-PCH
- 066_DDR4 DIMM CPU1 CHH-1
- 125_INTEL I210
- 184_CHANGE LIST
- 008_POWER GOOD/RESET DIAGRAM
- 067_DDR4 DIMM CPU1 CHH-2
- 126_INTEL I210 - RJ45
- 009_SYSTEM WARNING AND PROTECT
- 068_CPU SIDE BAND - HW STRAPS
- 127_INTEL I210 DECOUPLING
- 010_SYSTEM ERROR REPORTING
- 069_CPU SIDE BAND - ERR CIRCUIT
- 128_FAST PROCHOT
- 011_MEMORY WARNING AND PROTECT
- 070_CPU SIDE BAND - LEVEL SHIFT
- 129_HOT SWAP CIRCUIT
- 012_CPU XDP
- 071_CPU SIDE BAND - CAT. ERROR
- 130_P12V_PCIE_HDD
- 013_POWER ON SEQUENCE
- 072_CPU SIDE BAND - THERMTRIP
- 131_DB1900Z CLOCK BUFFER
- 014_POWER OFF SEQUENCE
- 073_CPU SIDE BAND -PROCHOT(1/2)
- 132_DB1900Z CLOCK TERMINATION1
- 015_RESISTOR DEFINITIONS
- 074_CPU SIDE BAND -PROCHOT(2/2)
- 133_DB1900Z CLOCK TERMINATION2
- 016_HOT PLUG BLOCK DIAGRAM
- 075_CPU SIDE BAND - DIMM_EVENT
- 134_CKMNG 202
- 017_PERIPHERAL BOARD DIAGRAM
- 076_CPU SIDE BAND - RST & PG
- 135_IRQ_ALERT
- 018_DDR SETTING
- 077_CPU SIDE BAND - PULL UP/DN
- 136_POWER CONNECTOR
- 019_UART SEL BLOCK DIAGRAM
- 078_CPU SIDE BAND - FIVR FAULT
- 137_CPLD
- 020_BIOS-SPI SWITCH DIAGRAM
- 079_MEZZ CONNECTOR
- 138_CPLD/FPGA & DECOUPLING (1/2
- 021_POWER SEQUENCE DIAGRAM
- 080_PCIE RISER
- 139_CPLD/FPGA & DECOUPLING (2/2
- 022_JTAG BLOCK DIAGRAM
- 081_MID-PLANE CONNECTOR
- 140_PVCCIN_CPU0_Controller
- 023_NVDIMM BLOCK DIAGRAM
- 082_WBG - CLOCK/MICS
- 141_PVCCIN_CPU0_MOSFET_1
- 024_CPU0 - MICS
- 083_WBG - DMI & USB
- 142_PVCCIN_CPU0_MOSFET_2
- 025_CPU0 - RESERVED PINS
- 084_WBG - SATA
- 143_PVCCIN_CPU0_Decoupling
- 026_CPU0 - DDR4 (CHANNEL A)
- 085_WBG - GPIO & SMB
- 144_PVCCIN_CPU1_Controller
- 027_CPU0 - DDR4 (CHANNEL B)
- 086_WBG - SPI
- 145_PVCCIN_CPU1_MOSFET_1
- 028_CPU0 - DDR4 (CHANNEL C)
- 087_WBG - CLOCK
- 146_PVCCIN_CPU1_MOSFET_2
- 029_CPU0 - DDR4 (CHANNEL D)
- 088_WBG - POWER
- 147_PVCCIN_CPU1_Decoupling
- 030_CPU0 - DMI & PCIE (1A-1B)
- 089_WBG - GROUND
- 148_PVDDQ_AB_Controller
- 031_CPU0 - PCIE (2A-2D)
- 090_WBG - FILTERING
- 149_PVDDQ_AB_MOSFET
- 032_CPU0 - PCIE (3A-3D)
- 091_WBG - DECOUPLING 1/2
- 150_PVTT_AB_MOSFET
- 033_CPU0 - QPI (1/2)
- 092_WBG - DECOUPLING 2/2
- 151_PVDDQ_AB_Decoupling
- 034_CPU0 - QPI (2/2)
- 093_WBG - STRAPPING/MISC
- 152_PVPP_AB_TPS53318
- 035_CPU0 - VCCIN & VDDQ
- 094_WBG - ISOLATION/TERMINATION
- 153_PVDDQ_CD_Controller
- 036_CPU0 - GROUND (1/2)
- 095_WBG - HEADERS
- 154_PVDDQ_CD_MOSFET
- 037_CPU0 - GROUND (2/2)
- 096_NGFF CONNECTOR
- 155_PVTT_CD_MOSFET
- 038_CPU1 - MICS
- 097_SATA CONNECTORS
- 156_PVDDQ_CD_Decoupling
- 039_CPU1 - RESERVED PINS
- 098_mSATA CONNECTOR
- 157_PVPP_CD_TPS53318
- 040_CPU1 - DDR4 (CHANNEL E)
- 099_USB 3.0/2.0 CONNECTORS
- 158_PVDDQ_EF_Controller
- 041_CPU1 - DDR4 (CHANNEL F)
- 100_miniSAS CONNECTORS_SATA
- 159_PVDDQ_EF_MOSFET
- 042_CPU1 - DDR4 (CHANNEL G)
- 101_miniSAS CONNECTORS_SATA_PWR
- 160_PVTT_EF_MOSFET
- 043_CPU1 - DDR4 (CHANNEL H)
- 102_WELLSBURG SPI FLASH
- 161_PVDDQ_EF_Decoupling
- 044_CPU1 - DMI & PCIE (1A-1B)
- 103_TPM HEADER
- 162_PVPP_EF_TPS53318
- 045_CPU1 - PCIE (2A-2D)
- 104_AST1010 I2C_UART_PWM
- 163_PVDDQ_GH_Controller
- 046_CPU1 - PCIE (3A-3D)
- 105_AST1010 - LPC_SPI_POWER
- 164_PVDDQ_GH_MOSFET
- 047_CPU1 - QPI (1/2)
- 106_AST1010 HEARTBEAT_ADC
- 165_PVTT_GH_MOSFET
- 048_CPU1 - QPI (2/2)
- 107_AST1010 & 2400 CO-LAYOUT
- 166_PVDDQ_GH_Decoupling
- 049_CPU1 - VCCIN & VDDQ
- 108_AST2400 PCIE_LPC_DDR3_I2C
- 167_PVPP_GH_TPS53318
- 050_CPU1 - GROUND (1/2)
- 109_AST2400 GPIO/RGMII/COM/SPI
- 168_PVCCIO_TPS53511
- 051_CPU1 - GROUND (2/2)
- 110_AST2400 CLK/VGA/USB/JTAG
- 169_P1V05_PCH_MPQ8632
- 052_DDR4 DIMM CPU0 CHA-1
- 111_AST2400 POWER
- 170_P1V05_STBY_PCH_TPS53511
- 053_DDR4 DIMM CPU0 CHA-2
- 112_AST2400 HARDWARE TRAPPING
- 171_P1V5_PCH_TPS74801
- 054_DDR4 DIMM CPU0 CHB-1
- 113_AST2400 ID SETTING
- 172_P1V8_STBY_TPS53312
- 055_DDR4 DIMM CPU0 CHB-2
- 114_COM PORT
- 173_P1V538_STBY_TPS74801
- 056_DDR4 DIMM CPU0 CHC-1
- 115_DEBUG PORT
- 174_P1V26_STBY_TPS74801
- 057_DDR4 DIMM CPU0 CHC-2
- 116_PECI
- 175_P5V_STBY_TPS53319
- 058_DDR4 DIMM CPU0 CHD-1
- 117_THERMAL SENSOR / V-BAT MONI
- 176_P3V3_MPQ8632
- 059_DDR4 DIMM CPU0 CHD-2
- 118_FAN - PWM
- 177_P3V3_STBY_TPS53312
sheet 158
- LEOPARD BW MAIN BOARD
- Rev : FAB4
- PCB : 15007
- BOM :
sheet 159
- SMBUS (3/4)
- FAB1 REV014 20150416
- FAB1 REV004 20150320
- Change to 72.24C64.I01
- PLATFORM VALIDATION TRACKING (FRU MEMORY)
  SMB ADDRESS: 0XA6
sheet 160
- SMBUS (1/4)
- PCA9617
  VCCA: 0.8 V to 5.5 V
  VCCB: 2.2 V to 5.5 V
- change to 71.09617.A0W
- change to 71.09617.A0W
- change to 71.09617.A0W
- change to 71.09617.A0W
